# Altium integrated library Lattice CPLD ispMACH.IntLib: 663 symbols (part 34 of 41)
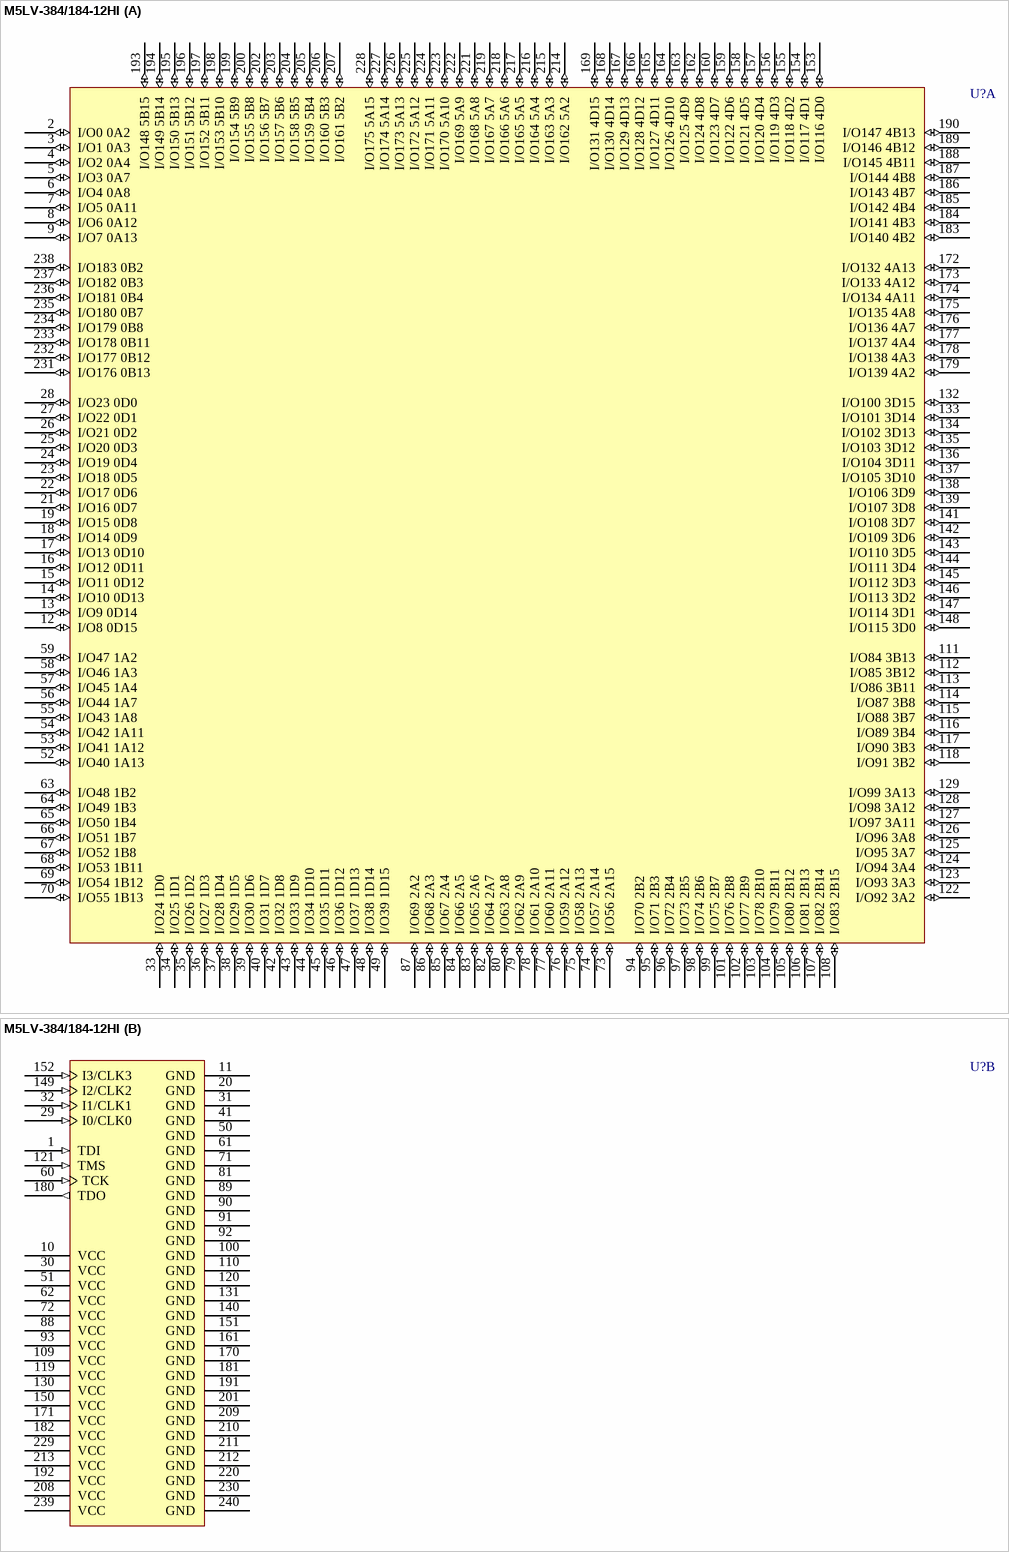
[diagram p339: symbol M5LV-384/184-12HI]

## M5LV-384/184-12HI
designator U?
High-Density and High-I/O Complex PLD
footprint PQFP240_N (Shrink QFP, 240-Leads, Body 32x32mm, Pitch 0.5mm, IPC Medium Density)
footprint PQFP240_L (Shrink QFP, 240-Leads, Body 32x32mm, Pitch 0.5mm, IPC High Density)
footprint PQFP240_M (Shrink QFP, 240-Leads, Body 32x32mm, Pitch 0.5mm, IPC Low Density)
3D model M5LV-PQFP240 (240-Pin Shrink Quad Flat Pack 0.5 mm Pitch)
part A pins: 2 I/O0 0A2 (io), 3 I/O1 0A3 (io), 4 I/O2 0A4 (io), 5 I/O3 0A7 (io), 6 I/O4 0A8 (io), 7 I/O5 0A11 (io), 8 I/O6 0A12 (io), 9 I/O7 0A13 (io), 12 I/O8 0D15 (io), 13 I/O9 0D14 (io), 14 I/O10 0D13 (io), 15 I/O11 0D12 (io), 16 I/O12 0D11 (io), 17 I/O13 0D10 (io), 18 I/O14 0D9 (io), 19 I/O15 0D8 (io), 21 I/O16 0D7 (io), 22 I/O17 0D6 (io), 23 I/O18 0D5 (io), 24 I/O19 0D4 (io), 25 I/O20 0D3 (io), 26 I/O21 0D2 (io), 27 I/O22 0D1 (io), 28 I/O23 0D0 (io), 33 I/O24 1D0 (io), 34 I/O25 1D1 (io), 35 I/O26 1D2 (io), 36 I/O27 1D3 (io), 37 I/O28 1D4 (io), 38 I/O29 1D5 (io), 39 I/O30 1D6 (io), 40 I/O31 1D7 (io), 42 I/O32 1D8 (io), 43 I/O33 1D9 (io), 44 I/O34 1D10 (io), 45 I/O35 1D11 (io), 46 I/O36 1D12 (io), 47 I/O37 1D13 (io), 48 I/O38 1D14 (io), 49 I/O39 1D15 (io), 52 I/O40 1A13 (io), 53 I/O41 1A12 (io), 54 I/O42 1A11 (io), 55 I/O43 1A8 (io), 56 I/O44 1A7 (io), 57 I/O45 1A4 (io), 58 I/O46 1A3 (io), 59 I/O47 1A2 (io), 63 I/O48 1B2 (io), 64 I/O49 1B3 (io), 65 I/O50 1B4 (io), 66 I/O51 1B7 (io), 67 I/O52 1B8 (io), 68 I/O53 1B11 (io), 69 I/O54 1B12 (io), 70 I/O55 1B13 (io), 73 I/O56 2A15 (io), 74 I/O57 2A14 (io), 75 I/O58 2A13 (io), 76 I/O59 2A12 (io), 77 I/O60 2A11 (io), 78 I/O61 2A10 (io), 79 I/O62 2A9 (io), 80 I/O63 2A8 (io), 82 I/O64 2A7 (io), 83 I/O65 2A6 (io), 84 I/O66 2A5 (io), 85 I/O67 2A4 (io), 86 I/O68 2A3 (io), 87 I/O69 2A2 (io), 94 I/O70 2B2 (io), 95 I/O71 2B3 (io), 96 I/O72 2B4 (io), 97 I/O73 2B5 (io), 98 I/O74 2B6 (io), 99 I/O75 2B7 (io), 101 I/O76 2B8 (io), 102 I/O77 2B9 (io), 103 I/O78 2B10 (io), 104 I/O79 2B11 (io), 105 I/O80 2B12 (io), 106 I/O81 2B13 (io), 107 I/O82 2B14 (io), 108 I/O83 2B15 (io), 111 I/O84 3B13 (io), 112 I/O85 3B12 (io), 113 I/O86 3B11 (io), 114 I/O87 3B8 (io), 115 I/O88 3B7 (io), 116 I/O89 3B4 (io), 117 I/O90 3B3 (io), 118 I/O91 3B2 (io), 122 I/O92 3A2 (io), 123 I/O93 3A3 (io), 124 I/O94 3A4 (io), 125 I/O95 3A7 (io), 126 I/O96 3A8 (io), 127 I/O97 3A11 (io), 128 I/O98 3A12 (io), 129 I/O99 3A13 (io), 132 I/O100 3D15 (io), 133 I/O101 3D14 (io), 134 I/O102 3D13 (io), 135 I/O103 3D12 (io), 136 I/O104 3D11 (io), 137 I/O105 3D10 (io), 138 I/O106 3D9 (io), 139 I/O107 3D8 (io), 141 I/O108 3D7 (io), 142 I/O109 3D6 (io), 143 I/O110 3D5 (io), 144 I/O111 3D4 (io), 145 I/O112 3D3 (io), 146 I/O113 3D2 (io), 147 I/O114 3D1 (io), 148 I/O115 3D0 (io), 153 I/O116 4D0 (io), 154 I/O117 4D1 (io), 155 I/O118 4D2 (io), 156 I/O119 4D3 (io), 157 I/O120 4D4 (io), 158 I/O121 4D5 (io), 159 I/O122 4D6 (io), 160 I/O123 4D7 (io), 162 I/O124 4D8 (io), 163 I/O125 4D9 (io), 164 I/O126 4D10 (io), 165 I/O127 4D11 (io), 166 I/O128 4D12 (io), 167 I/O129 4D13 (io), 168 I/O130 4D14 (io), 169 I/O131 4D15 (io), 172 I/O132 4A13 (io), 173 I/O133 4A12 (io), 174 I/O134 4A11 (io), 175 I/O135 4A8 (io), 176 I/O136 4A7 (io), 177 I/O137 4A4 (io), 178 I/O138 4A3 (io), 179 I/O139 4A2 (io), 183 I/O140 4B2 (io), 184 I/O141 4B3 (io), 185 I/O142 4B4 (io), 186 I/O143 4B7 (io), 187 I/O144 4B8 (io), 188 I/O145 4B11 (io), 189 I/O146 4B12 (io), 190 I/O147 4B13 (io), 193 I/O148 5B15 (io), 194 I/O149 5B14 (io), 195 I/O150 5B13 (io), 196 I/O151 5B12 (io), 197 I/O152 5B11 (io), 198 I/O153 5B10 (io), 199 I/O154 5B9 (io), 200 I/O155 5B8 (io), 202 I/O156 5B7 (io), 203 I/O157 5B6 (io), 204 I/O158 5B5 (io), 205 I/O159 5B4 (io), 206 I/O160 5B3 (io), 207 I/O161 5B2 (io), 214 I/O162 5A2 (io), 215 I/O163 5A3 (io), 216 I/O164 5A4 (io), 217 I/O165 5A5 (io), 218 I/O166 5A6 (io), 219 I/O167 5A7 (io), 221 I/O168 5A8 (io), 222 I/O169 5A9 (io), 223 I/O170 5A10 (io), 224 I/O171 5A11 (io), 225 I/O172 5A12 (io), 226 I/O173 5A13 (io), 227 I/O174 5A14 (io), 228 I/O175 5A15 (io), 231 I/O176 0B13 (io), 232 I/O177 0B12 (io), 233 I/O178 0B11 (io), 234 I/O179 0B8 (io), 235 I/O180 0B7 (io), 236 I/O181 0B4 (io), 237 I/O182 0B3 (io), 238 I/O183 0B2 (io)
part B pins: 1 TDI (in), 10 VCC (power), 11 GND (power), 20 GND (power), 29 I0/CLK0 (in), 30 VCC (power), 31 GND (power), 32 I1/CLK1 (in), 41 GND (power), 50 GND (power), 51 VCC (power), 60 TCK (in), 61 GND (power), 62 VCC (power), 71 GND (power), 72 VCC (power), 81 GND (power), 88 VCC (power), 89 GND (power), 90 GND (power), 91 GND (power), 92 GND (power), 93 VCC (power), 100 GND (power), 109 VCC (power), 110 GND (power), 119 VCC (power), 120 GND (power), 121 TMS (in), 130 VCC (power), 131 GND (power), 140 GND (power), 149 I2/CLK2 (in), 150 VCC (power), 151 GND (power), 152 I3/CLK3 (in), 161 GND (power), 170 GND (power), 171 VCC (power), 180 TDO (out), 181 GND (power), 182 VCC (power), 191 GND (power), 192 VCC (power), 201 GND (power), 208 VCC (power), 209 GND (power), 210 GND (power), 211 GND (power), 212 GND (power), 213 VCC (power), 220 GND (power), 229 VCC (power), 230 GND (power), 239 VCC (power), 240 GND (power)

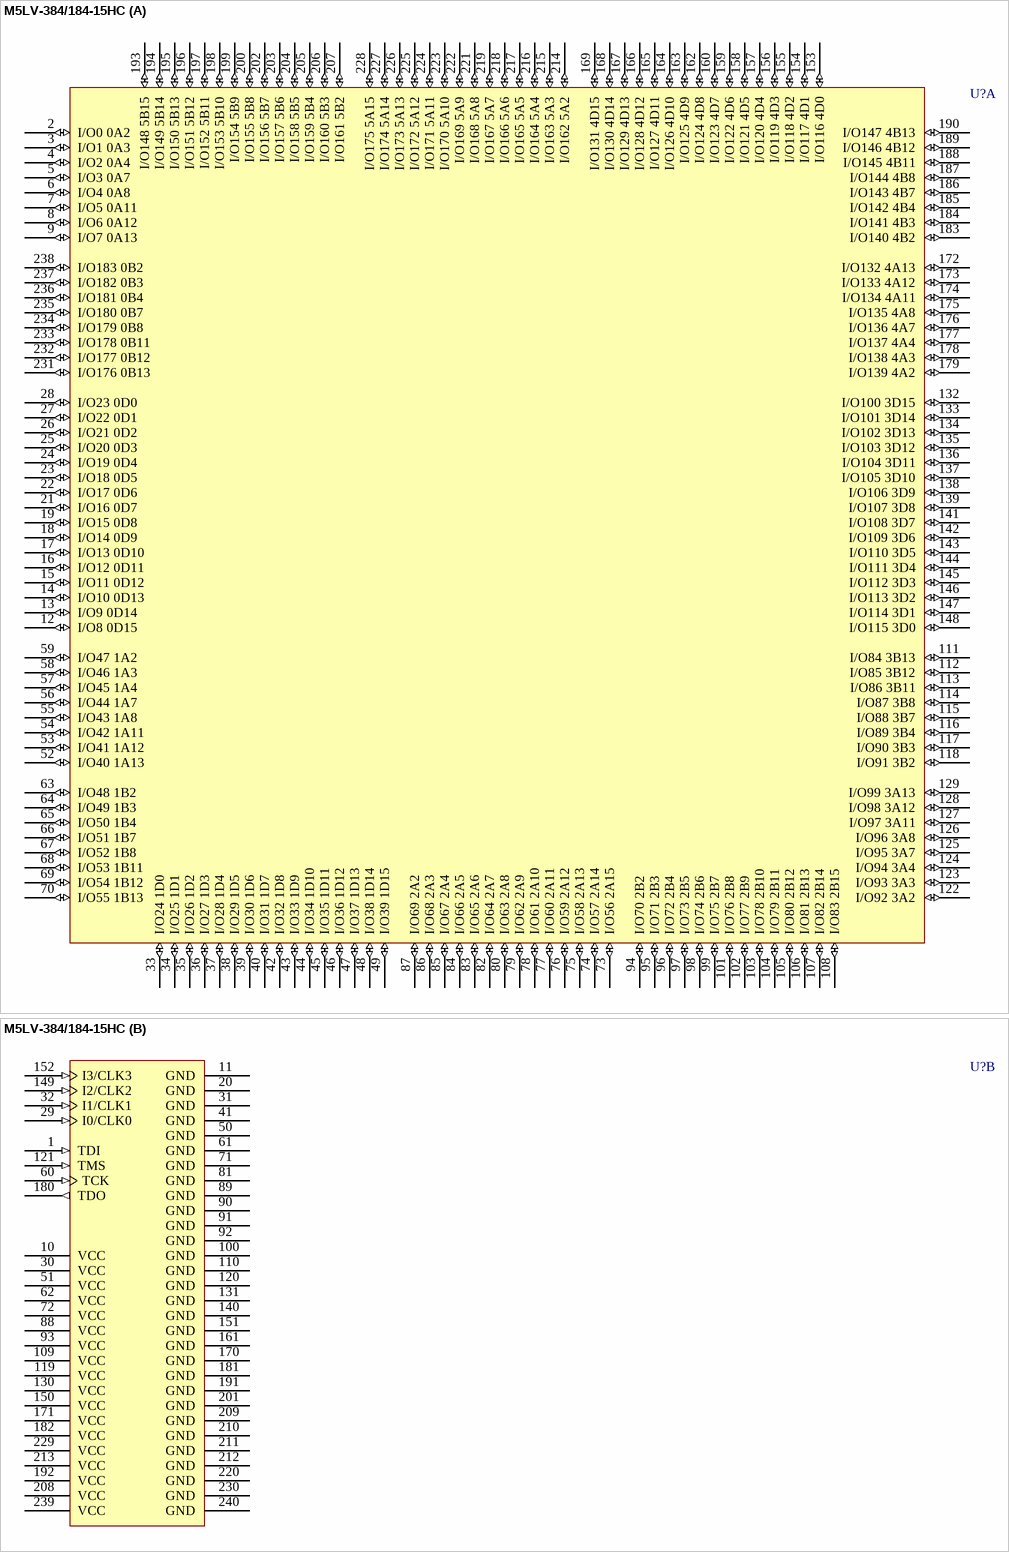
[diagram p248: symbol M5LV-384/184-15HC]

## M5LV-384/184-15HC
designator U?
High-Density and High-I/O Complex PLD
footprint PQFP240_N (Shrink QFP, 240-Leads, Body 32x32mm, Pitch 0.5mm, IPC Medium Density)
footprint PQFP240_L (Shrink QFP, 240-Leads, Body 32x32mm, Pitch 0.5mm, IPC High Density)
footprint PQFP240_M (Shrink QFP, 240-Leads, Body 32x32mm, Pitch 0.5mm, IPC Low Density)
3D model M5LV-PQFP240 (240-Pin Shrink Quad Flat Pack 0.5 mm Pitch)
part A pins: 2 I/O0 0A2 (io), 3 I/O1 0A3 (io), 4 I/O2 0A4 (io), 5 I/O3 0A7 (io), 6 I/O4 0A8 (io), 7 I/O5 0A11 (io), 8 I/O6 0A12 (io), 9 I/O7 0A13 (io), 12 I/O8 0D15 (io), 13 I/O9 0D14 (io), 14 I/O10 0D13 (io), 15 I/O11 0D12 (io), 16 I/O12 0D11 (io), 17 I/O13 0D10 (io), 18 I/O14 0D9 (io), 19 I/O15 0D8 (io), 21 I/O16 0D7 (io), 22 I/O17 0D6 (io), 23 I/O18 0D5 (io), 24 I/O19 0D4 (io), 25 I/O20 0D3 (io), 26 I/O21 0D2 (io), 27 I/O22 0D1 (io), 28 I/O23 0D0 (io), 33 I/O24 1D0 (io), 34 I/O25 1D1 (io), 35 I/O26 1D2 (io), 36 I/O27 1D3 (io), 37 I/O28 1D4 (io), 38 I/O29 1D5 (io), 39 I/O30 1D6 (io), 40 I/O31 1D7 (io), 42 I/O32 1D8 (io), 43 I/O33 1D9 (io), 44 I/O34 1D10 (io), 45 I/O35 1D11 (io), 46 I/O36 1D12 (io), 47 I/O37 1D13 (io), 48 I/O38 1D14 (io), 49 I/O39 1D15 (io), 52 I/O40 1A13 (io), 53 I/O41 1A12 (io), 54 I/O42 1A11 (io), 55 I/O43 1A8 (io), 56 I/O44 1A7 (io), 57 I/O45 1A4 (io), 58 I/O46 1A3 (io), 59 I/O47 1A2 (io), 63 I/O48 1B2 (io), 64 I/O49 1B3 (io), 65 I/O50 1B4 (io), 66 I/O51 1B7 (io), 67 I/O52 1B8 (io), 68 I/O53 1B11 (io), 69 I/O54 1B12 (io), 70 I/O55 1B13 (io), 73 I/O56 2A15 (io), 74 I/O57 2A14 (io), 75 I/O58 2A13 (io), 76 I/O59 2A12 (io), 77 I/O60 2A11 (io), 78 I/O61 2A10 (io), 79 I/O62 2A9 (io), 80 I/O63 2A8 (io), 82 I/O64 2A7 (io), 83 I/O65 2A6 (io), 84 I/O66 2A5 (io), 85 I/O67 2A4 (io), 86 I/O68 2A3 (io), 87 I/O69 2A2 (io), 94 I/O70 2B2 (io), 95 I/O71 2B3 (io), 96 I/O72 2B4 (io), 97 I/O73 2B5 (io), 98 I/O74 2B6 (io), 99 I/O75 2B7 (io), 101 I/O76 2B8 (io), 102 I/O77 2B9 (io), 103 I/O78 2B10 (io), 104 I/O79 2B11 (io), 105 I/O80 2B12 (io), 106 I/O81 2B13 (io), 107 I/O82 2B14 (io), 108 I/O83 2B15 (io), 111 I/O84 3B13 (io), 112 I/O85 3B12 (io), 113 I/O86 3B11 (io), 114 I/O87 3B8 (io), 115 I/O88 3B7 (io), 116 I/O89 3B4 (io), 117 I/O90 3B3 (io), 118 I/O91 3B2 (io), 122 I/O92 3A2 (io), 123 I/O93 3A3 (io), 124 I/O94 3A4 (io), 125 I/O95 3A7 (io), 126 I/O96 3A8 (io), 127 I/O97 3A11 (io), 128 I/O98 3A12 (io), 129 I/O99 3A13 (io), 132 I/O100 3D15 (io), 133 I/O101 3D14 (io), 134 I/O102 3D13 (io), 135 I/O103 3D12 (io), 136 I/O104 3D11 (io), 137 I/O105 3D10 (io), 138 I/O106 3D9 (io), 139 I/O107 3D8 (io), 141 I/O108 3D7 (io), 142 I/O109 3D6 (io), 143 I/O110 3D5 (io), 144 I/O111 3D4 (io), 145 I/O112 3D3 (io), 146 I/O113 3D2 (io), 147 I/O114 3D1 (io), 148 I/O115 3D0 (io), 153 I/O116 4D0 (io), 154 I/O117 4D1 (io), 155 I/O118 4D2 (io), 156 I/O119 4D3 (io), 157 I/O120 4D4 (io), 158 I/O121 4D5 (io), 159 I/O122 4D6 (io), 160 I/O123 4D7 (io), 162 I/O124 4D8 (io), 163 I/O125 4D9 (io), 164 I/O126 4D10 (io), 165 I/O127 4D11 (io), 166 I/O128 4D12 (io), 167 I/O129 4D13 (io), 168 I/O130 4D14 (io), 169 I/O131 4D15 (io), 172 I/O132 4A13 (io), 173 I/O133 4A12 (io), 174 I/O134 4A11 (io), 175 I/O135 4A8 (io), 176 I/O136 4A7 (io), 177 I/O137 4A4 (io), 178 I/O138 4A3 (io), 179 I/O139 4A2 (io), 183 I/O140 4B2 (io), 184 I/O141 4B3 (io), 185 I/O142 4B4 (io), 186 I/O143 4B7 (io), 187 I/O144 4B8 (io), 188 I/O145 4B11 (io), 189 I/O146 4B12 (io), 190 I/O147 4B13 (io), 193 I/O148 5B15 (io), 194 I/O149 5B14 (io), 195 I/O150 5B13 (io), 196 I/O151 5B12 (io), 197 I/O152 5B11 (io), 198 I/O153 5B10 (io), 199 I/O154 5B9 (io), 200 I/O155 5B8 (io), 202 I/O156 5B7 (io), 203 I/O157 5B6 (io), 204 I/O158 5B5 (io), 205 I/O159 5B4 (io), 206 I/O160 5B3 (io), 207 I/O161 5B2 (io), 214 I/O162 5A2 (io), 215 I/O163 5A3 (io), 216 I/O164 5A4 (io), 217 I/O165 5A5 (io), 218 I/O166 5A6 (io), 219 I/O167 5A7 (io), 221 I/O168 5A8 (io), 222 I/O169 5A9 (io), 223 I/O170 5A10 (io), 224 I/O171 5A11 (io), 225 I/O172 5A12 (io), 226 I/O173 5A13 (io), 227 I/O174 5A14 (io), 228 I/O175 5A15 (io), 231 I/O176 0B13 (io), 232 I/O177 0B12 (io), 233 I/O178 0B11 (io), 234 I/O179 0B8 (io), 235 I/O180 0B7 (io), 236 I/O181 0B4 (io), 237 I/O182 0B3 (io), 238 I/O183 0B2 (io)
part B pins: 1 TDI (in), 10 VCC (power), 11 GND (power), 20 GND (power), 29 I0/CLK0 (in), 30 VCC (power), 31 GND (power), 32 I1/CLK1 (in), 41 GND (power), 50 GND (power), 51 VCC (power), 60 TCK (in), 61 GND (power), 62 VCC (power), 71 GND (power), 72 VCC (power), 81 GND (power), 88 VCC (power), 89 GND (power), 90 GND (power), 91 GND (power), 92 GND (power), 93 VCC (power), 100 GND (power), 109 VCC (power), 110 GND (power), 119 VCC (power), 120 GND (power), 121 TMS (in), 130 VCC (power), 131 GND (power), 140 GND (power), 149 I2/CLK2 (in), 150 VCC (power), 151 GND (power), 152 I3/CLK3 (in), 161 GND (power), 170 GND (power), 171 VCC (power), 180 TDO (out), 181 GND (power), 182 VCC (power), 191 GND (power), 192 VCC (power), 201 GND (power), 208 VCC (power), 209 GND (power), 210 GND (power), 211 GND (power), 212 GND (power), 213 VCC (power), 220 GND (power), 229 VCC (power), 230 GND (power), 239 VCC (power), 240 GND (power)

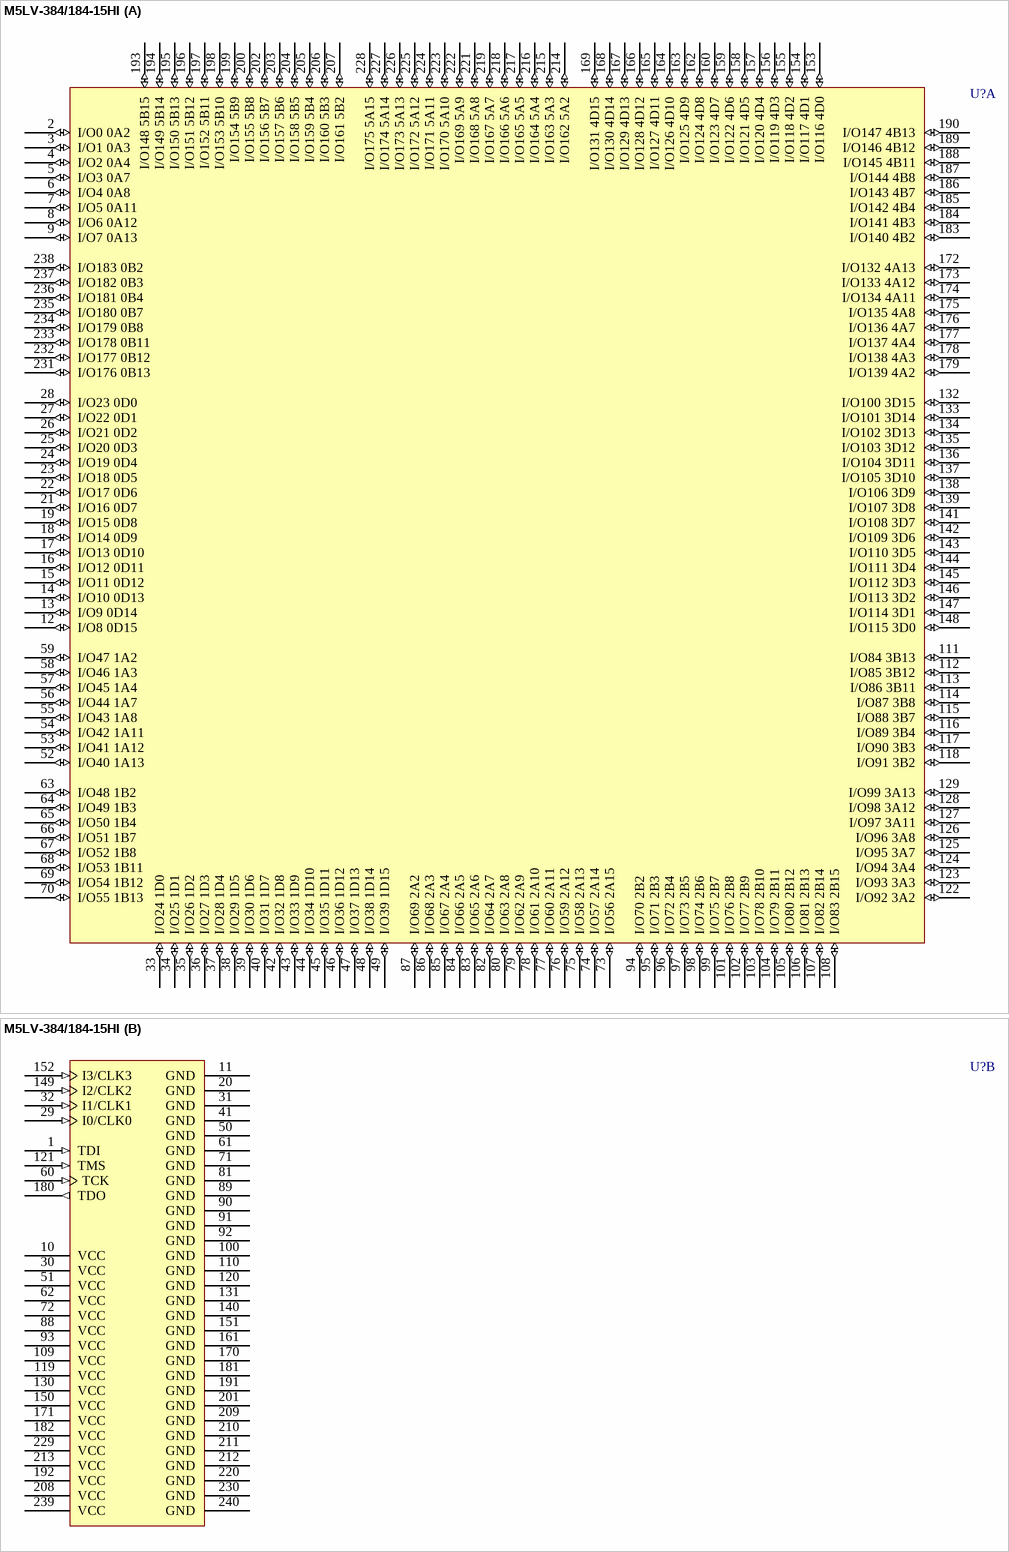
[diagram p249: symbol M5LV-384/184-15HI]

## M5LV-384/184-15HI
designator U?
High-Density and High-I/O Complex PLD
footprint PQFP240_N (Shrink QFP, 240-Leads, Body 32x32mm, Pitch 0.5mm, IPC Medium Density)
footprint PQFP240_L (Shrink QFP, 240-Leads, Body 32x32mm, Pitch 0.5mm, IPC High Density)
footprint PQFP240_M (Shrink QFP, 240-Leads, Body 32x32mm, Pitch 0.5mm, IPC Low Density)
3D model M5LV-PQFP240 (240-Pin Shrink Quad Flat Pack 0.5 mm Pitch)
part A pins: 2 I/O0 0A2 (io), 3 I/O1 0A3 (io), 4 I/O2 0A4 (io), 5 I/O3 0A7 (io), 6 I/O4 0A8 (io), 7 I/O5 0A11 (io), 8 I/O6 0A12 (io), 9 I/O7 0A13 (io), 12 I/O8 0D15 (io), 13 I/O9 0D14 (io), 14 I/O10 0D13 (io), 15 I/O11 0D12 (io), 16 I/O12 0D11 (io), 17 I/O13 0D10 (io), 18 I/O14 0D9 (io), 19 I/O15 0D8 (io), 21 I/O16 0D7 (io), 22 I/O17 0D6 (io), 23 I/O18 0D5 (io), 24 I/O19 0D4 (io), 25 I/O20 0D3 (io), 26 I/O21 0D2 (io), 27 I/O22 0D1 (io), 28 I/O23 0D0 (io), 33 I/O24 1D0 (io), 34 I/O25 1D1 (io), 35 I/O26 1D2 (io), 36 I/O27 1D3 (io), 37 I/O28 1D4 (io), 38 I/O29 1D5 (io), 39 I/O30 1D6 (io), 40 I/O31 1D7 (io), 42 I/O32 1D8 (io), 43 I/O33 1D9 (io), 44 I/O34 1D10 (io), 45 I/O35 1D11 (io), 46 I/O36 1D12 (io), 47 I/O37 1D13 (io), 48 I/O38 1D14 (io), 49 I/O39 1D15 (io), 52 I/O40 1A13 (io), 53 I/O41 1A12 (io), 54 I/O42 1A11 (io), 55 I/O43 1A8 (io), 56 I/O44 1A7 (io), 57 I/O45 1A4 (io), 58 I/O46 1A3 (io), 59 I/O47 1A2 (io), 63 I/O48 1B2 (io), 64 I/O49 1B3 (io), 65 I/O50 1B4 (io), 66 I/O51 1B7 (io), 67 I/O52 1B8 (io), 68 I/O53 1B11 (io), 69 I/O54 1B12 (io), 70 I/O55 1B13 (io), 73 I/O56 2A15 (io), 74 I/O57 2A14 (io), 75 I/O58 2A13 (io), 76 I/O59 2A12 (io), 77 I/O60 2A11 (io), 78 I/O61 2A10 (io), 79 I/O62 2A9 (io), 80 I/O63 2A8 (io), 82 I/O64 2A7 (io), 83 I/O65 2A6 (io), 84 I/O66 2A5 (io), 85 I/O67 2A4 (io), 86 I/O68 2A3 (io), 87 I/O69 2A2 (io), 94 I/O70 2B2 (io), 95 I/O71 2B3 (io), 96 I/O72 2B4 (io), 97 I/O73 2B5 (io), 98 I/O74 2B6 (io), 99 I/O75 2B7 (io), 101 I/O76 2B8 (io), 102 I/O77 2B9 (io), 103 I/O78 2B10 (io), 104 I/O79 2B11 (io), 105 I/O80 2B12 (io), 106 I/O81 2B13 (io), 107 I/O82 2B14 (io), 108 I/O83 2B15 (io), 111 I/O84 3B13 (io), 112 I/O85 3B12 (io), 113 I/O86 3B11 (io), 114 I/O87 3B8 (io), 115 I/O88 3B7 (io), 116 I/O89 3B4 (io), 117 I/O90 3B3 (io), 118 I/O91 3B2 (io), 122 I/O92 3A2 (io), 123 I/O93 3A3 (io), 124 I/O94 3A4 (io), 125 I/O95 3A7 (io), 126 I/O96 3A8 (io), 127 I/O97 3A11 (io), 128 I/O98 3A12 (io), 129 I/O99 3A13 (io), 132 I/O100 3D15 (io), 133 I/O101 3D14 (io), 134 I/O102 3D13 (io), 135 I/O103 3D12 (io), 136 I/O104 3D11 (io), 137 I/O105 3D10 (io), 138 I/O106 3D9 (io), 139 I/O107 3D8 (io), 141 I/O108 3D7 (io), 142 I/O109 3D6 (io), 143 I/O110 3D5 (io), 144 I/O111 3D4 (io), 145 I/O112 3D3 (io), 146 I/O113 3D2 (io), 147 I/O114 3D1 (io), 148 I/O115 3D0 (io), 153 I/O116 4D0 (io), 154 I/O117 4D1 (io), 155 I/O118 4D2 (io), 156 I/O119 4D3 (io), 157 I/O120 4D4 (io), 158 I/O121 4D5 (io), 159 I/O122 4D6 (io), 160 I/O123 4D7 (io), 162 I/O124 4D8 (io), 163 I/O125 4D9 (io), 164 I/O126 4D10 (io), 165 I/O127 4D11 (io), 166 I/O128 4D12 (io), 167 I/O129 4D13 (io), 168 I/O130 4D14 (io), 169 I/O131 4D15 (io), 172 I/O132 4A13 (io), 173 I/O133 4A12 (io), 174 I/O134 4A11 (io), 175 I/O135 4A8 (io), 176 I/O136 4A7 (io), 177 I/O137 4A4 (io), 178 I/O138 4A3 (io), 179 I/O139 4A2 (io), 183 I/O140 4B2 (io), 184 I/O141 4B3 (io), 185 I/O142 4B4 (io), 186 I/O143 4B7 (io), 187 I/O144 4B8 (io), 188 I/O145 4B11 (io), 189 I/O146 4B12 (io), 190 I/O147 4B13 (io), 193 I/O148 5B15 (io), 194 I/O149 5B14 (io), 195 I/O150 5B13 (io), 196 I/O151 5B12 (io), 197 I/O152 5B11 (io), 198 I/O153 5B10 (io), 199 I/O154 5B9 (io), 200 I/O155 5B8 (io), 202 I/O156 5B7 (io), 203 I/O157 5B6 (io), 204 I/O158 5B5 (io), 205 I/O159 5B4 (io), 206 I/O160 5B3 (io), 207 I/O161 5B2 (io), 214 I/O162 5A2 (io), 215 I/O163 5A3 (io), 216 I/O164 5A4 (io), 217 I/O165 5A5 (io), 218 I/O166 5A6 (io), 219 I/O167 5A7 (io), 221 I/O168 5A8 (io), 222 I/O169 5A9 (io), 223 I/O170 5A10 (io), 224 I/O171 5A11 (io), 225 I/O172 5A12 (io), 226 I/O173 5A13 (io), 227 I/O174 5A14 (io), 228 I/O175 5A15 (io), 231 I/O176 0B13 (io), 232 I/O177 0B12 (io), 233 I/O178 0B11 (io), 234 I/O179 0B8 (io), 235 I/O180 0B7 (io), 236 I/O181 0B4 (io), 237 I/O182 0B3 (io), 238 I/O183 0B2 (io)
part B pins: 1 TDI (in), 10 VCC (power), 11 GND (power), 20 GND (power), 29 I0/CLK0 (in), 30 VCC (power), 31 GND (power), 32 I1/CLK1 (in), 41 GND (power), 50 GND (power), 51 VCC (power), 60 TCK (in), 61 GND (power), 62 VCC (power), 71 GND (power), 72 VCC (power), 81 GND (power), 88 VCC (power), 89 GND (power), 90 GND (power), 91 GND (power), 92 GND (power), 93 VCC (power), 100 GND (power), 109 VCC (power), 110 GND (power), 119 VCC (power), 120 GND (power), 121 TMS (in), 130 VCC (power), 131 GND (power), 140 GND (power), 149 I2/CLK2 (in), 150 VCC (power), 151 GND (power), 152 I3/CLK3 (in), 161 GND (power), 170 GND (power), 171 VCC (power), 180 TDO (out), 181 GND (power), 182 VCC (power), 191 GND (power), 192 VCC (power), 201 GND (power), 208 VCC (power), 209 GND (power), 210 GND (power), 211 GND (power), 212 GND (power), 213 VCC (power), 220 GND (power), 229 VCC (power), 230 GND (power), 239 VCC (power), 240 GND (power)

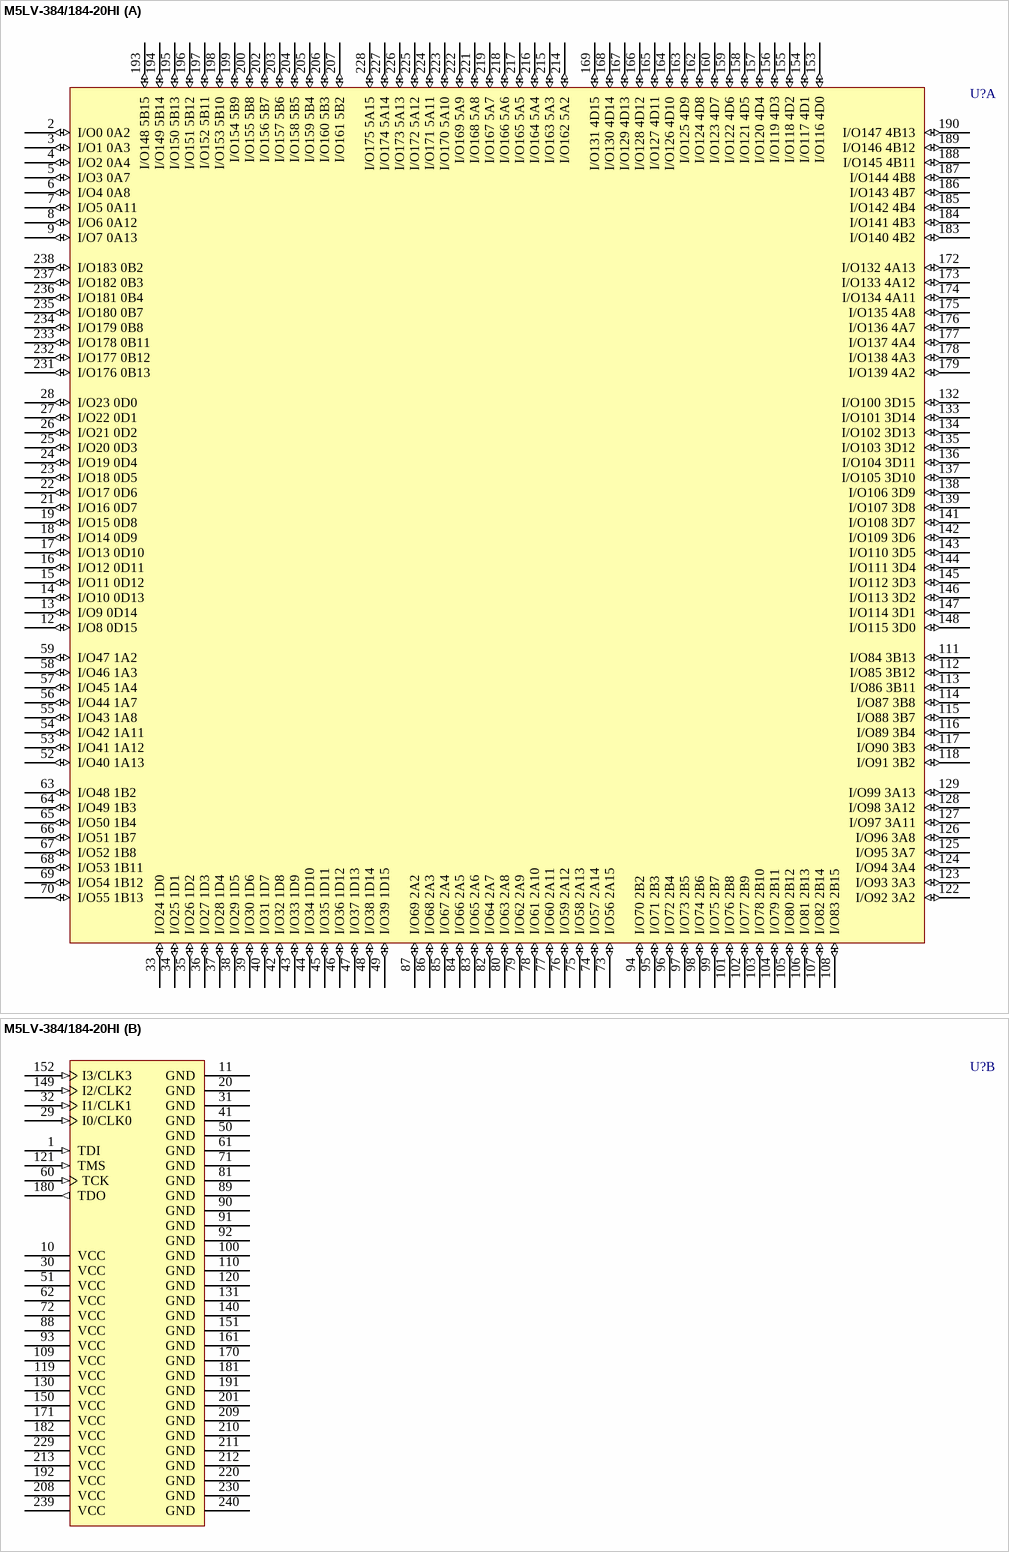
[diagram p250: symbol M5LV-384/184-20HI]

## M5LV-384/184-20HI
designator U?
High-Density and High-I/O Complex PLD
footprint PQFP240_N (Shrink QFP, 240-Leads, Body 32x32mm, Pitch 0.5mm, IPC Medium Density)
footprint PQFP240_L (Shrink QFP, 240-Leads, Body 32x32mm, Pitch 0.5mm, IPC High Density)
footprint PQFP240_M (Shrink QFP, 240-Leads, Body 32x32mm, Pitch 0.5mm, IPC Low Density)
3D model M5LV-PQFP240 (240-Pin Shrink Quad Flat Pack 0.5 mm Pitch)
part A pins: 2 I/O0 0A2 (io), 3 I/O1 0A3 (io), 4 I/O2 0A4 (io), 5 I/O3 0A7 (io), 6 I/O4 0A8 (io), 7 I/O5 0A11 (io), 8 I/O6 0A12 (io), 9 I/O7 0A13 (io), 12 I/O8 0D15 (io), 13 I/O9 0D14 (io), 14 I/O10 0D13 (io), 15 I/O11 0D12 (io), 16 I/O12 0D11 (io), 17 I/O13 0D10 (io), 18 I/O14 0D9 (io), 19 I/O15 0D8 (io), 21 I/O16 0D7 (io), 22 I/O17 0D6 (io), 23 I/O18 0D5 (io), 24 I/O19 0D4 (io), 25 I/O20 0D3 (io), 26 I/O21 0D2 (io), 27 I/O22 0D1 (io), 28 I/O23 0D0 (io), 33 I/O24 1D0 (io), 34 I/O25 1D1 (io), 35 I/O26 1D2 (io), 36 I/O27 1D3 (io), 37 I/O28 1D4 (io), 38 I/O29 1D5 (io), 39 I/O30 1D6 (io), 40 I/O31 1D7 (io), 42 I/O32 1D8 (io), 43 I/O33 1D9 (io), 44 I/O34 1D10 (io), 45 I/O35 1D11 (io), 46 I/O36 1D12 (io), 47 I/O37 1D13 (io), 48 I/O38 1D14 (io), 49 I/O39 1D15 (io), 52 I/O40 1A13 (io), 53 I/O41 1A12 (io), 54 I/O42 1A11 (io), 55 I/O43 1A8 (io), 56 I/O44 1A7 (io), 57 I/O45 1A4 (io), 58 I/O46 1A3 (io), 59 I/O47 1A2 (io), 63 I/O48 1B2 (io), 64 I/O49 1B3 (io), 65 I/O50 1B4 (io), 66 I/O51 1B7 (io), 67 I/O52 1B8 (io), 68 I/O53 1B11 (io), 69 I/O54 1B12 (io), 70 I/O55 1B13 (io), 73 I/O56 2A15 (io), 74 I/O57 2A14 (io), 75 I/O58 2A13 (io), 76 I/O59 2A12 (io), 77 I/O60 2A11 (io), 78 I/O61 2A10 (io), 79 I/O62 2A9 (io), 80 I/O63 2A8 (io), 82 I/O64 2A7 (io), 83 I/O65 2A6 (io), 84 I/O66 2A5 (io), 85 I/O67 2A4 (io), 86 I/O68 2A3 (io), 87 I/O69 2A2 (io), 94 I/O70 2B2 (io), 95 I/O71 2B3 (io), 96 I/O72 2B4 (io), 97 I/O73 2B5 (io), 98 I/O74 2B6 (io), 99 I/O75 2B7 (io), 101 I/O76 2B8 (io), 102 I/O77 2B9 (io), 103 I/O78 2B10 (io), 104 I/O79 2B11 (io), 105 I/O80 2B12 (io), 106 I/O81 2B13 (io), 107 I/O82 2B14 (io), 108 I/O83 2B15 (io), 111 I/O84 3B13 (io), 112 I/O85 3B12 (io), 113 I/O86 3B11 (io), 114 I/O87 3B8 (io), 115 I/O88 3B7 (io), 116 I/O89 3B4 (io), 117 I/O90 3B3 (io), 118 I/O91 3B2 (io), 122 I/O92 3A2 (io), 123 I/O93 3A3 (io), 124 I/O94 3A4 (io), 125 I/O95 3A7 (io), 126 I/O96 3A8 (io), 127 I/O97 3A11 (io), 128 I/O98 3A12 (io), 129 I/O99 3A13 (io), 132 I/O100 3D15 (io), 133 I/O101 3D14 (io), 134 I/O102 3D13 (io), 135 I/O103 3D12 (io), 136 I/O104 3D11 (io), 137 I/O105 3D10 (io), 138 I/O106 3D9 (io), 139 I/O107 3D8 (io), 141 I/O108 3D7 (io), 142 I/O109 3D6 (io), 143 I/O110 3D5 (io), 144 I/O111 3D4 (io), 145 I/O112 3D3 (io), 146 I/O113 3D2 (io), 147 I/O114 3D1 (io), 148 I/O115 3D0 (io), 153 I/O116 4D0 (io), 154 I/O117 4D1 (io), 155 I/O118 4D2 (io), 156 I/O119 4D3 (io), 157 I/O120 4D4 (io), 158 I/O121 4D5 (io), 159 I/O122 4D6 (io), 160 I/O123 4D7 (io), 162 I/O124 4D8 (io), 163 I/O125 4D9 (io), 164 I/O126 4D10 (io), 165 I/O127 4D11 (io), 166 I/O128 4D12 (io), 167 I/O129 4D13 (io), 168 I/O130 4D14 (io), 169 I/O131 4D15 (io), 172 I/O132 4A13 (io), 173 I/O133 4A12 (io), 174 I/O134 4A11 (io), 175 I/O135 4A8 (io), 176 I/O136 4A7 (io), 177 I/O137 4A4 (io), 178 I/O138 4A3 (io), 179 I/O139 4A2 (io), 183 I/O140 4B2 (io), 184 I/O141 4B3 (io), 185 I/O142 4B4 (io), 186 I/O143 4B7 (io), 187 I/O144 4B8 (io), 188 I/O145 4B11 (io), 189 I/O146 4B12 (io), 190 I/O147 4B13 (io), 193 I/O148 5B15 (io), 194 I/O149 5B14 (io), 195 I/O150 5B13 (io), 196 I/O151 5B12 (io), 197 I/O152 5B11 (io), 198 I/O153 5B10 (io), 199 I/O154 5B9 (io), 200 I/O155 5B8 (io), 202 I/O156 5B7 (io), 203 I/O157 5B6 (io), 204 I/O158 5B5 (io), 205 I/O159 5B4 (io), 206 I/O160 5B3 (io), 207 I/O161 5B2 (io), 214 I/O162 5A2 (io), 215 I/O163 5A3 (io), 216 I/O164 5A4 (io), 217 I/O165 5A5 (io), 218 I/O166 5A6 (io), 219 I/O167 5A7 (io), 221 I/O168 5A8 (io), 222 I/O169 5A9 (io), 223 I/O170 5A10 (io), 224 I/O171 5A11 (io), 225 I/O172 5A12 (io), 226 I/O173 5A13 (io), 227 I/O174 5A14 (io), 228 I/O175 5A15 (io), 231 I/O176 0B13 (io), 232 I/O177 0B12 (io), 233 I/O178 0B11 (io), 234 I/O179 0B8 (io), 235 I/O180 0B7 (io), 236 I/O181 0B4 (io), 237 I/O182 0B3 (io), 238 I/O183 0B2 (io)
part B pins: 1 TDI (in), 10 VCC (power), 11 GND (power), 20 GND (power), 29 I0/CLK0 (in), 30 VCC (power), 31 GND (power), 32 I1/CLK1 (in), 41 GND (power), 50 GND (power), 51 VCC (power), 60 TCK (in), 61 GND (power), 62 VCC (power), 71 GND (power), 72 VCC (power), 81 GND (power), 88 VCC (power), 89 GND (power), 90 GND (power), 91 GND (power), 92 GND (power), 93 VCC (power), 100 GND (power), 109 VCC (power), 110 GND (power), 119 VCC (power), 120 GND (power), 121 TMS (in), 130 VCC (power), 131 GND (power), 140 GND (power), 149 I2/CLK2 (in), 150 VCC (power), 151 GND (power), 152 I3/CLK3 (in), 161 GND (power), 170 GND (power), 171 VCC (power), 180 TDO (out), 181 GND (power), 182 VCC (power), 191 GND (power), 192 VCC (power), 201 GND (power), 208 VCC (power), 209 GND (power), 210 GND (power), 211 GND (power), 212 GND (power), 213 VCC (power), 220 GND (power), 229 VCC (power), 230 GND (power), 239 VCC (power), 240 GND (power)

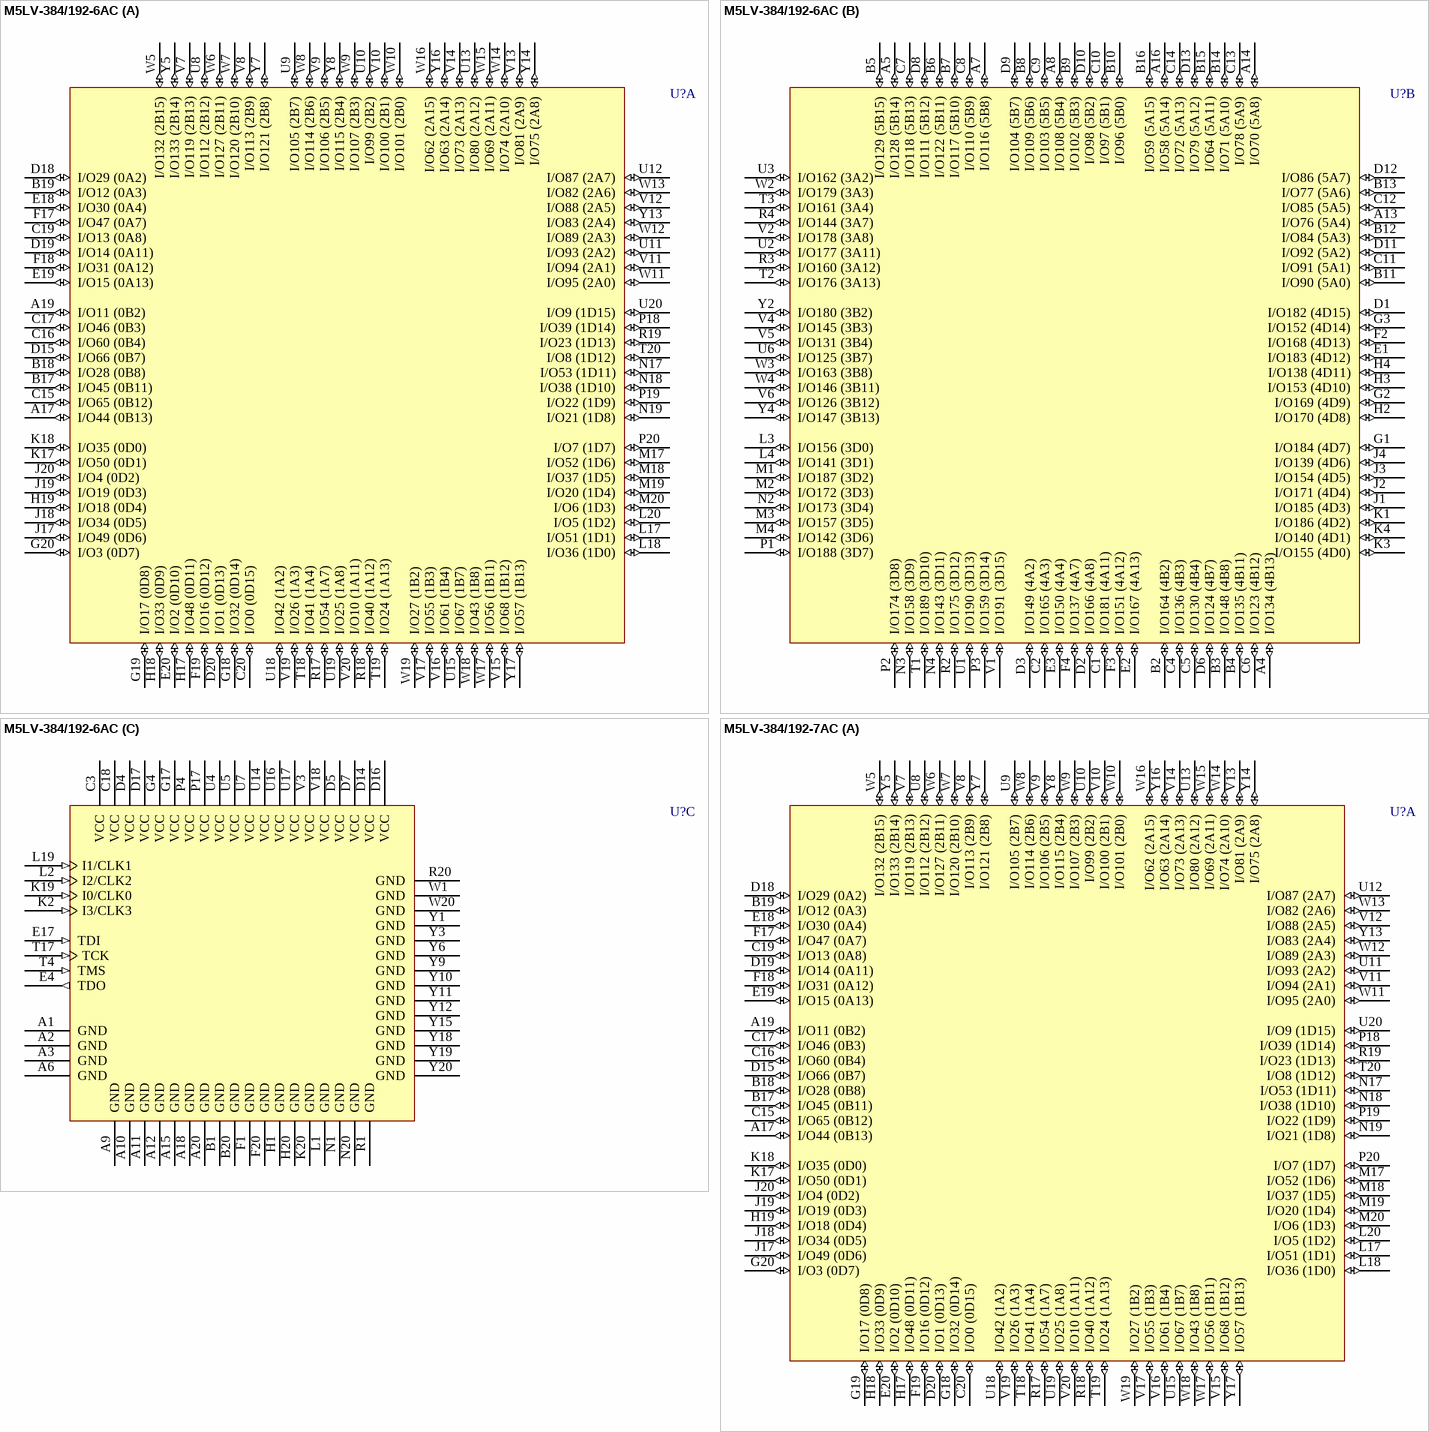
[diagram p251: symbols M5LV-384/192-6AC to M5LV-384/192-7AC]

## M5LV-384/192-6AC
designator U?
High-Density and High-I/O Complex PLD
footprint SBGA256 (BGA, 256-Leads, Body 27x27mm, Pitch 1.27mm)
3D model M5LV-SBGA256 (256-Ball Super Ball Grid Array (SBGA256))
part A pins: A17 I/O44 (0B13) (io), A19 I/O11 (0B2) (io), B17 I/O45 (0B11) (io), B18 I/O28 (0B8) (io), B19 I/O12 (0A3) (io), C15 I/O65 (0B12) (io), C16 I/O60 (0B4) (io), C17 I/O46 (0B3) (io), C19 I/O13 (0A8) (io), C20 I/O0 (0D15) (io), D15 I/O66 (0B7) (io), D18 I/O29 (0A2) (io), D19 I/O14 (0A11) (io), D20 I/O1 (0D13) (io), E18 I/O30 (0A4) (io), E19 I/O15 (0A13) (io), E20 I/O2 (0D10) (io), F17 I/O47 (0A7) (io), F18 I/O31 (0A12) (io), F19 I/O16 (0D12) (io), G18 I/O32 (0D14) (io), G19 I/O17 (0D8) (io), G20 I/O3 (0D7) (io), H17 I/O48 (0D11) (io), H18 I/O33 (0D9) (io), H19 I/O18 (0D4) (io), J17 I/O49 (0D6) (io), J18 I/O34 (0D5) (io), J19 I/O19 (0D3) (io), J20 I/O4 (0D2) (io), K17 I/O50 (0D1) (io), K18 I/O35 (0D0) (io), L17 I/O51 (1D1) (io), L18 I/O36 (1D0) (io), L20 I/O5 (1D2) (io), M17 I/O52 (1D6) (io), M18 I/O37 (1D5) (io), M19 I/O20 (1D4) (io), M20 I/O6 (1D3) (io), N17 I/O53 (1D11) (io), N18 I/O38 (1D10) (io), N19 I/O21 (1D8) (io), P18 I/O39 (1D14) (io), P19 I/O22 (1D9) (io), P20 I/O7 (1D7) (io), R17 I/O54 (1A7) (io), R18 I/O40 (1A12) (io), R19 I/O23 (1D13) (io), T18 I/O41 (1A4) (io), T19 I/O24 (1A13) (io), T20 I/O8 (1D12) (io), U8 I/O112 (2B12) (io), U9 I/O105 (2B7) (io), U10 I/O99 (2B2) (io), U11 I/O93 (2A2) (io), U12 I/O87 (2A7) (io), U13 I/O80 (2A12) (io), U15 I/O67 (1B7) (io), U18 I/O42 (1A2) (io), U19 I/O25 (1A8) (io), U20 I/O9 (1D15) (io), V7 I/O119 (2B13) (io), V8 I/O113 (2B9) (io), V9 I/O106 (2B5) (io), V10 I/O100 (2B1) (io), V11 I/O94 (2A1) (io), V12 I/O88 (2A5) (io), V13 I/O81 (2A9) (io), V14 I/O73 (2A13) (io), V15 I/O68 (1B12) (io), V16 I/O61 (1B4) (io), V17 I/O55 (1B3) (io), V19 I/O26 (1A3) (io), V20 I/O10 (1A11) (io), W5 I/O132 (2B15) (io), W6 I/O127 (2B11) (io), W7 I/O120 (2B10) (io), W8 I/O114 (2B6) (io), W9 I/O107 (2B3) (io), W10 I/O101 (2B0) (io), W11 I/O95 (2A0) (io), W12 I/O89 (2A3) (io), W13 I/O82 (2A6) (io), W14 I/O74 (2A10) (io), W15 I/O69 (2A11) (io), W16 I/O62 (2A15) (io), W17 I/O56 (1B11) (io), W18 I/O43 (1B8) (io), W19 I/O27 (1B2) (io), Y5 I/O133 (2B14) (io), Y7 I/O121 (2B8) (io), Y8 I/O115 (2B4) (io), Y13 I/O83 (2A4) (io), Y14 I/O75 (2A8) (io), Y16 I/O63 (2A14) (io), Y17 I/O57 (1B13) (io)
part B pins: A4 I/O134 (4B13) (io), A5 I/O128 (5B14) (io), A7 I/O116 (5B8) (io), A8 I/O108 (5B4) (io), A13 I/O76 (5A4) (io), A14 I/O70 (5A8) (io), A16 I/O58 (5A14) (io), B2 I/O164 (4B2) (io), B3 I/O148 (4B8) (io), B4 I/O135 (4B11) (io), B5 I/O129 (5B15) (io), B6 I/O122 (5B11) (io), B7 I/O117 (5B10) (io), B8 I/O109 (5B6) (io), B9 I/O102 (5B3) (io), B10 I/O96 (5B0) (io), B11 I/O90 (5A0) (io), B12 I/O84 (5A3) (io), B13 I/O77 (5A6) (io), B14 I/O71 (5A10) (io), B15 I/O64 (5A11) (io), B16 I/O59 (5A15) (io), C1 I/O181 (4A11) (io), C2 I/O165 (4A3) (io), C4 I/O136 (4B3) (io), C5 I/O130 (4B4) (io), C6 I/O123 (4B12) (io), C7 I/O118 (5B13) (io), C8 I/O110 (5B9) (io), C9 I/O103 (5B5) (io), C10 I/O97 (5B1) (io), C11 I/O91 (5A1) (io), C12 I/O85 (5A5) (io), C13 I/O78 (5A9) (io), C14 I/O72 (5A13) (io), D1 I/O182 (4D15) (io), D2 I/O166 (4A8) (io), D3 I/O149 (4A2) (io), D6 I/O124 (4B7) (io), D8 I/O111 (5B12) (io), D9 I/O104 (5B7) (io), D10 I/O98 (5B2) (io), D11 I/O92 (5A2) (io), D12 I/O86 (5A7) (io), D13 I/O79 (5A12) (io), E1 I/O183 (4D12) (io), E2 I/O167 (4A13) (io), E3 I/O150 (4A4) (io), F2 I/O168 (4D13) (io), F3 I/O151 (4A12) (io), F4 I/O137 (4A7) (io), G1 I/O184 (4D7) (io), G2 I/O169 (4D9) (io), G3 I/O152 (4D14) (io), H2 I/O170 (4D8) (io), H3 I/O153 (4D10) (io), H4 I/O138 (4D11) (io), J1 I/O185 (4D3) (io), J2 I/O171 (4D4) (io), J3 I/O154 (4D5) (io), J4 I/O139 (4D6) (io), K1 I/O186 (4D2) (io), K3 I/O155 (4D0) (io), K4 I/O140 (4D1) (io), L3 I/O156 (3D0) (io), L4 I/O141 (3D1) (io), M1 I/O187 (3D2) (io), M2 I/O172 (3D3) (io), M3 I/O157 (3D5) (io), M4 I/O142 (3D6) (io), N2 I/O173 (3D4) (io), N3 I/O158 (3D9) (io), N4 I/O143 (3D11) (io), P1 I/O188 (3D7) (io), P2 I/O174 (3D8) (io), P3 I/O159 (3D14) (io), R2 I/O175 (3D12) (io), R3 I/O160 (3A12) (io), R4 I/O144 (3A7) (io), T1 I/O189 (3D10) (io), T2 I/O176 (3A13) (io), T3 I/O161 (3A4) (io), U1 I/O190 (3D13) (io), U2 I/O177 (3A11) (io), U3 I/O162 (3A2) (io), U6 I/O125 (3B7) (io), V1 I/O191 (3D15) (io), V2 I/O178 (3A8) (io), V4 I/O145 (3B3) (io), V5 I/O131 (3B4) (io), V6 I/O126 (3B12) (io), W2 I/O179 (3A3) (io), W3 I/O163 (3B8) (io), W4 I/O146 (3B11) (io), Y2 I/O180 (3B2) (io), Y4 I/O147 (3B13) (io)
part C pins: A1 GND (power), A2 GND (power), A3 GND (power), A6 GND (power), A9 GND (power), A10 GND (power), A11 GND (power), A12 GND (power), A15 GND (power), A18 GND (power), A20 GND (power), B1 GND (power), B20 GND (power), C3 VCC (power), C18 VCC (power), D4 VCC (power), D5 VCC (power), D7 VCC (power), D14 VCC (power), D16 VCC (power), D17 VCC (power), E4 TDO (out), E17 TDI (in), F1 GND (power), F20 GND (power), G4 VCC (power), G17 VCC (power), H1 GND (power), H20 GND (power), K2 I3/CLK3 (in), K19 I0/CLK0 (in), K20 GND (power), L1 GND (power), L2 I2/CLK2 (in), L19 I1/CLK1 (in), N1 GND (power), N20 GND (power), P4 VCC (power), P17 VCC (power), R1 GND (power), R20 GND (power), T4 TMS (in), T17 TCK (in), U4 VCC (power), U5 VCC (power), U7 VCC (power), U14 VCC (power), U16 VCC (power), U17 VCC (power), V3 VCC (power), V18 VCC (power), W1 GND (power), W20 GND (power), Y1 GND (power), Y3 GND (power), Y6 GND (power), Y9 GND (power), Y10 GND (power), Y11 GND (power), Y12 GND (power), Y15 GND (power), Y18 GND (power), Y19 GND (power), Y20 GND (power)

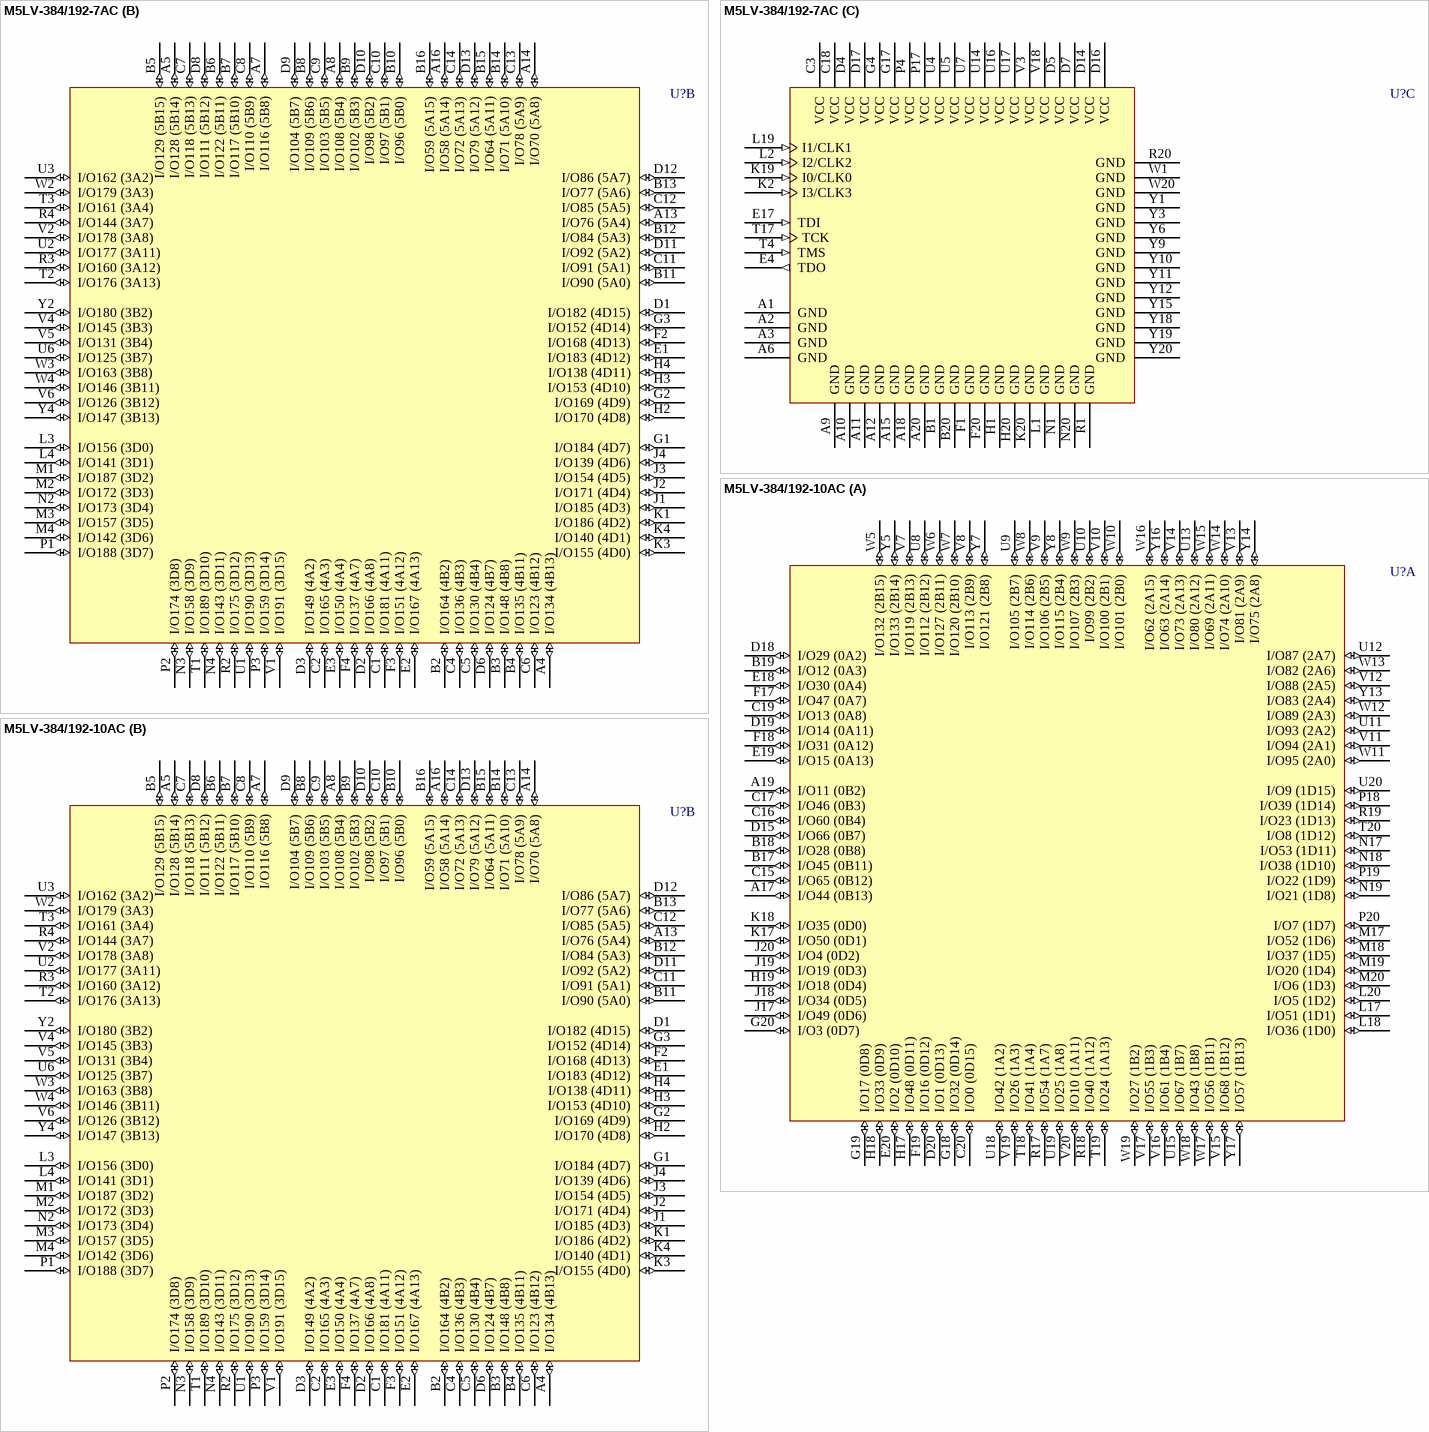
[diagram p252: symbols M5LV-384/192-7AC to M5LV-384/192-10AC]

## M5LV-384/192-7AC
designator U?
High-Density and High-I/O Complex PLD
footprint SBGA256 (BGA, 256-Leads, Body 27x27mm, Pitch 1.27mm)
3D model M5LV-SBGA256 (256-Ball Super Ball Grid Array (SBGA256))
part A pins: A17 I/O44 (0B13) (io), A19 I/O11 (0B2) (io), B17 I/O45 (0B11) (io), B18 I/O28 (0B8) (io), B19 I/O12 (0A3) (io), C15 I/O65 (0B12) (io), C16 I/O60 (0B4) (io), C17 I/O46 (0B3) (io), C19 I/O13 (0A8) (io), C20 I/O0 (0D15) (io), D15 I/O66 (0B7) (io), D18 I/O29 (0A2) (io), D19 I/O14 (0A11) (io), D20 I/O1 (0D13) (io), E18 I/O30 (0A4) (io), E19 I/O15 (0A13) (io), E20 I/O2 (0D10) (io), F17 I/O47 (0A7) (io), F18 I/O31 (0A12) (io), F19 I/O16 (0D12) (io), G18 I/O32 (0D14) (io), G19 I/O17 (0D8) (io), G20 I/O3 (0D7) (io), H17 I/O48 (0D11) (io), H18 I/O33 (0D9) (io), H19 I/O18 (0D4) (io), J17 I/O49 (0D6) (io), J18 I/O34 (0D5) (io), J19 I/O19 (0D3) (io), J20 I/O4 (0D2) (io), K17 I/O50 (0D1) (io), K18 I/O35 (0D0) (io), L17 I/O51 (1D1) (io), L18 I/O36 (1D0) (io), L20 I/O5 (1D2) (io), M17 I/O52 (1D6) (io), M18 I/O37 (1D5) (io), M19 I/O20 (1D4) (io), M20 I/O6 (1D3) (io), N17 I/O53 (1D11) (io), N18 I/O38 (1D10) (io), N19 I/O21 (1D8) (io), P18 I/O39 (1D14) (io), P19 I/O22 (1D9) (io), P20 I/O7 (1D7) (io), R17 I/O54 (1A7) (io), R18 I/O40 (1A12) (io), R19 I/O23 (1D13) (io), T18 I/O41 (1A4) (io), T19 I/O24 (1A13) (io), T20 I/O8 (1D12) (io), U8 I/O112 (2B12) (io), U9 I/O105 (2B7) (io), U10 I/O99 (2B2) (io), U11 I/O93 (2A2) (io), U12 I/O87 (2A7) (io), U13 I/O80 (2A12) (io), U15 I/O67 (1B7) (io), U18 I/O42 (1A2) (io), U19 I/O25 (1A8) (io), U20 I/O9 (1D15) (io), V7 I/O119 (2B13) (io), V8 I/O113 (2B9) (io), V9 I/O106 (2B5) (io), V10 I/O100 (2B1) (io), V11 I/O94 (2A1) (io), V12 I/O88 (2A5) (io), V13 I/O81 (2A9) (io), V14 I/O73 (2A13) (io), V15 I/O68 (1B12) (io), V16 I/O61 (1B4) (io), V17 I/O55 (1B3) (io), V19 I/O26 (1A3) (io), V20 I/O10 (1A11) (io), W5 I/O132 (2B15) (io), W6 I/O127 (2B11) (io), W7 I/O120 (2B10) (io), W8 I/O114 (2B6) (io), W9 I/O107 (2B3) (io), W10 I/O101 (2B0) (io), W11 I/O95 (2A0) (io), W12 I/O89 (2A3) (io), W13 I/O82 (2A6) (io), W14 I/O74 (2A10) (io), W15 I/O69 (2A11) (io), W16 I/O62 (2A15) (io), W17 I/O56 (1B11) (io), W18 I/O43 (1B8) (io), W19 I/O27 (1B2) (io), Y5 I/O133 (2B14) (io), Y7 I/O121 (2B8) (io), Y8 I/O115 (2B4) (io), Y13 I/O83 (2A4) (io), Y14 I/O75 (2A8) (io), Y16 I/O63 (2A14) (io), Y17 I/O57 (1B13) (io)
part B pins: A4 I/O134 (4B13) (io), A5 I/O128 (5B14) (io), A7 I/O116 (5B8) (io), A8 I/O108 (5B4) (io), A13 I/O76 (5A4) (io), A14 I/O70 (5A8) (io), A16 I/O58 (5A14) (io), B2 I/O164 (4B2) (io), B3 I/O148 (4B8) (io), B4 I/O135 (4B11) (io), B5 I/O129 (5B15) (io), B6 I/O122 (5B11) (io), B7 I/O117 (5B10) (io), B8 I/O109 (5B6) (io), B9 I/O102 (5B3) (io), B10 I/O96 (5B0) (io), B11 I/O90 (5A0) (io), B12 I/O84 (5A3) (io), B13 I/O77 (5A6) (io), B14 I/O71 (5A10) (io), B15 I/O64 (5A11) (io), B16 I/O59 (5A15) (io), C1 I/O181 (4A11) (io), C2 I/O165 (4A3) (io), C4 I/O136 (4B3) (io), C5 I/O130 (4B4) (io), C6 I/O123 (4B12) (io), C7 I/O118 (5B13) (io), C8 I/O110 (5B9) (io), C9 I/O103 (5B5) (io), C10 I/O97 (5B1) (io), C11 I/O91 (5A1) (io), C12 I/O85 (5A5) (io), C13 I/O78 (5A9) (io), C14 I/O72 (5A13) (io), D1 I/O182 (4D15) (io), D2 I/O166 (4A8) (io), D3 I/O149 (4A2) (io), D6 I/O124 (4B7) (io), D8 I/O111 (5B12) (io), D9 I/O104 (5B7) (io), D10 I/O98 (5B2) (io), D11 I/O92 (5A2) (io), D12 I/O86 (5A7) (io), D13 I/O79 (5A12) (io), E1 I/O183 (4D12) (io), E2 I/O167 (4A13) (io), E3 I/O150 (4A4) (io), F2 I/O168 (4D13) (io), F3 I/O151 (4A12) (io), F4 I/O137 (4A7) (io), G1 I/O184 (4D7) (io), G2 I/O169 (4D9) (io), G3 I/O152 (4D14) (io), H2 I/O170 (4D8) (io), H3 I/O153 (4D10) (io), H4 I/O138 (4D11) (io), J1 I/O185 (4D3) (io), J2 I/O171 (4D4) (io), J3 I/O154 (4D5) (io), J4 I/O139 (4D6) (io), K1 I/O186 (4D2) (io), K3 I/O155 (4D0) (io), K4 I/O140 (4D1) (io), L3 I/O156 (3D0) (io), L4 I/O141 (3D1) (io), M1 I/O187 (3D2) (io), M2 I/O172 (3D3) (io), M3 I/O157 (3D5) (io), M4 I/O142 (3D6) (io), N2 I/O173 (3D4) (io), N3 I/O158 (3D9) (io), N4 I/O143 (3D11) (io), P1 I/O188 (3D7) (io), P2 I/O174 (3D8) (io), P3 I/O159 (3D14) (io), R2 I/O175 (3D12) (io), R3 I/O160 (3A12) (io), R4 I/O144 (3A7) (io), T1 I/O189 (3D10) (io), T2 I/O176 (3A13) (io), T3 I/O161 (3A4) (io), U1 I/O190 (3D13) (io), U2 I/O177 (3A11) (io), U3 I/O162 (3A2) (io), U6 I/O125 (3B7) (io), V1 I/O191 (3D15) (io), V2 I/O178 (3A8) (io), V4 I/O145 (3B3) (io), V5 I/O131 (3B4) (io), V6 I/O126 (3B12) (io), W2 I/O179 (3A3) (io), W3 I/O163 (3B8) (io), W4 I/O146 (3B11) (io), Y2 I/O180 (3B2) (io), Y4 I/O147 (3B13) (io)
part C pins: A1 GND (power), A2 GND (power), A3 GND (power), A6 GND (power), A9 GND (power), A10 GND (power), A11 GND (power), A12 GND (power), A15 GND (power), A18 GND (power), A20 GND (power), B1 GND (power), B20 GND (power), C3 VCC (power), C18 VCC (power), D4 VCC (power), D5 VCC (power), D7 VCC (power), D14 VCC (power), D16 VCC (power), D17 VCC (power), E4 TDO (out), E17 TDI (in), F1 GND (power), F20 GND (power), G4 VCC (power), G17 VCC (power), H1 GND (power), H20 GND (power), K2 I3/CLK3 (in), K19 I0/CLK0 (in), K20 GND (power), L1 GND (power), L2 I2/CLK2 (in), L19 I1/CLK1 (in), N1 GND (power), N20 GND (power), P4 VCC (power), P17 VCC (power), R1 GND (power), R20 GND (power), T4 TMS (in), T17 TCK (in), U4 VCC (power), U5 VCC (power), U7 VCC (power), U14 VCC (power), U16 VCC (power), U17 VCC (power), V3 VCC (power), V18 VCC (power), W1 GND (power), W20 GND (power), Y1 GND (power), Y3 GND (power), Y6 GND (power), Y9 GND (power), Y10 GND (power), Y11 GND (power), Y12 GND (power), Y15 GND (power), Y18 GND (power), Y19 GND (power), Y20 GND (power)

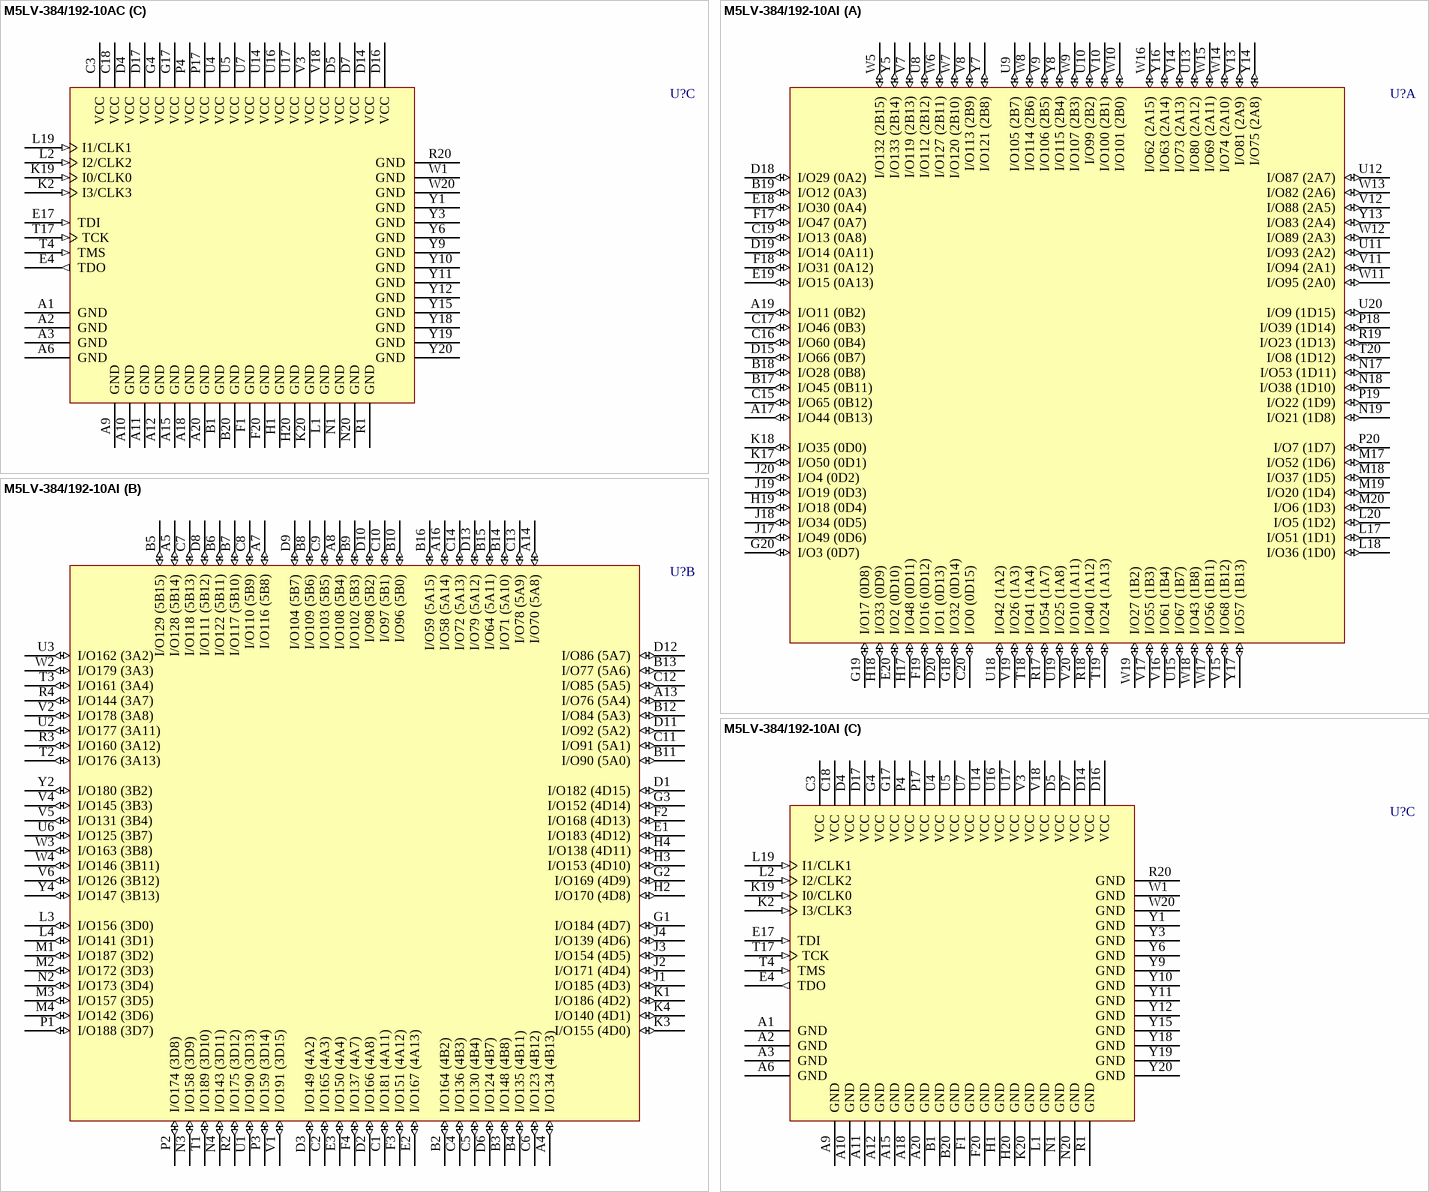
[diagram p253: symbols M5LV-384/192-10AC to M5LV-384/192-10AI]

## M5LV-384/192-10AC
designator U?
High-Density and High-I/O Complex PLD
footprint SBGA256 (BGA, 256-Leads, Body 27x27mm, Pitch 1.27mm)
3D model M5LV-SBGA256 (256-Ball Super Ball Grid Array (SBGA256))
part A pins: A17 I/O44 (0B13) (io), A19 I/O11 (0B2) (io), B17 I/O45 (0B11) (io), B18 I/O28 (0B8) (io), B19 I/O12 (0A3) (io), C15 I/O65 (0B12) (io), C16 I/O60 (0B4) (io), C17 I/O46 (0B3) (io), C19 I/O13 (0A8) (io), C20 I/O0 (0D15) (io), D15 I/O66 (0B7) (io), D18 I/O29 (0A2) (io), D19 I/O14 (0A11) (io), D20 I/O1 (0D13) (io), E18 I/O30 (0A4) (io), E19 I/O15 (0A13) (io), E20 I/O2 (0D10) (io), F17 I/O47 (0A7) (io), F18 I/O31 (0A12) (io), F19 I/O16 (0D12) (io), G18 I/O32 (0D14) (io), G19 I/O17 (0D8) (io), G20 I/O3 (0D7) (io), H17 I/O48 (0D11) (io), H18 I/O33 (0D9) (io), H19 I/O18 (0D4) (io), J17 I/O49 (0D6) (io), J18 I/O34 (0D5) (io), J19 I/O19 (0D3) (io), J20 I/O4 (0D2) (io), K17 I/O50 (0D1) (io), K18 I/O35 (0D0) (io), L17 I/O51 (1D1) (io), L18 I/O36 (1D0) (io), L20 I/O5 (1D2) (io), M17 I/O52 (1D6) (io), M18 I/O37 (1D5) (io), M19 I/O20 (1D4) (io), M20 I/O6 (1D3) (io), N17 I/O53 (1D11) (io), N18 I/O38 (1D10) (io), N19 I/O21 (1D8) (io), P18 I/O39 (1D14) (io), P19 I/O22 (1D9) (io), P20 I/O7 (1D7) (io), R17 I/O54 (1A7) (io), R18 I/O40 (1A12) (io), R19 I/O23 (1D13) (io), T18 I/O41 (1A4) (io), T19 I/O24 (1A13) (io), T20 I/O8 (1D12) (io), U8 I/O112 (2B12) (io), U9 I/O105 (2B7) (io), U10 I/O99 (2B2) (io), U11 I/O93 (2A2) (io), U12 I/O87 (2A7) (io), U13 I/O80 (2A12) (io), U15 I/O67 (1B7) (io), U18 I/O42 (1A2) (io), U19 I/O25 (1A8) (io), U20 I/O9 (1D15) (io), V7 I/O119 (2B13) (io), V8 I/O113 (2B9) (io), V9 I/O106 (2B5) (io), V10 I/O100 (2B1) (io), V11 I/O94 (2A1) (io), V12 I/O88 (2A5) (io), V13 I/O81 (2A9) (io), V14 I/O73 (2A13) (io), V15 I/O68 (1B12) (io), V16 I/O61 (1B4) (io), V17 I/O55 (1B3) (io), V19 I/O26 (1A3) (io), V20 I/O10 (1A11) (io), W5 I/O132 (2B15) (io), W6 I/O127 (2B11) (io), W7 I/O120 (2B10) (io), W8 I/O114 (2B6) (io), W9 I/O107 (2B3) (io), W10 I/O101 (2B0) (io), W11 I/O95 (2A0) (io), W12 I/O89 (2A3) (io), W13 I/O82 (2A6) (io), W14 I/O74 (2A10) (io), W15 I/O69 (2A11) (io), W16 I/O62 (2A15) (io), W17 I/O56 (1B11) (io), W18 I/O43 (1B8) (io), W19 I/O27 (1B2) (io), Y5 I/O133 (2B14) (io), Y7 I/O121 (2B8) (io), Y8 I/O115 (2B4) (io), Y13 I/O83 (2A4) (io), Y14 I/O75 (2A8) (io), Y16 I/O63 (2A14) (io), Y17 I/O57 (1B13) (io)
part B pins: A4 I/O134 (4B13) (io), A5 I/O128 (5B14) (io), A7 I/O116 (5B8) (io), A8 I/O108 (5B4) (io), A13 I/O76 (5A4) (io), A14 I/O70 (5A8) (io), A16 I/O58 (5A14) (io), B2 I/O164 (4B2) (io), B3 I/O148 (4B8) (io), B4 I/O135 (4B11) (io), B5 I/O129 (5B15) (io), B6 I/O122 (5B11) (io), B7 I/O117 (5B10) (io), B8 I/O109 (5B6) (io), B9 I/O102 (5B3) (io), B10 I/O96 (5B0) (io), B11 I/O90 (5A0) (io), B12 I/O84 (5A3) (io), B13 I/O77 (5A6) (io), B14 I/O71 (5A10) (io), B15 I/O64 (5A11) (io), B16 I/O59 (5A15) (io), C1 I/O181 (4A11) (io), C2 I/O165 (4A3) (io), C4 I/O136 (4B3) (io), C5 I/O130 (4B4) (io), C6 I/O123 (4B12) (io), C7 I/O118 (5B13) (io), C8 I/O110 (5B9) (io), C9 I/O103 (5B5) (io), C10 I/O97 (5B1) (io), C11 I/O91 (5A1) (io), C12 I/O85 (5A5) (io), C13 I/O78 (5A9) (io), C14 I/O72 (5A13) (io), D1 I/O182 (4D15) (io), D2 I/O166 (4A8) (io), D3 I/O149 (4A2) (io), D6 I/O124 (4B7) (io), D8 I/O111 (5B12) (io), D9 I/O104 (5B7) (io), D10 I/O98 (5B2) (io), D11 I/O92 (5A2) (io), D12 I/O86 (5A7) (io), D13 I/O79 (5A12) (io), E1 I/O183 (4D12) (io), E2 I/O167 (4A13) (io), E3 I/O150 (4A4) (io), F2 I/O168 (4D13) (io), F3 I/O151 (4A12) (io), F4 I/O137 (4A7) (io), G1 I/O184 (4D7) (io), G2 I/O169 (4D9) (io), G3 I/O152 (4D14) (io), H2 I/O170 (4D8) (io), H3 I/O153 (4D10) (io), H4 I/O138 (4D11) (io), J1 I/O185 (4D3) (io), J2 I/O171 (4D4) (io), J3 I/O154 (4D5) (io), J4 I/O139 (4D6) (io), K1 I/O186 (4D2) (io), K3 I/O155 (4D0) (io), K4 I/O140 (4D1) (io), L3 I/O156 (3D0) (io), L4 I/O141 (3D1) (io), M1 I/O187 (3D2) (io), M2 I/O172 (3D3) (io), M3 I/O157 (3D5) (io), M4 I/O142 (3D6) (io), N2 I/O173 (3D4) (io), N3 I/O158 (3D9) (io), N4 I/O143 (3D11) (io), P1 I/O188 (3D7) (io), P2 I/O174 (3D8) (io), P3 I/O159 (3D14) (io), R2 I/O175 (3D12) (io), R3 I/O160 (3A12) (io), R4 I/O144 (3A7) (io), T1 I/O189 (3D10) (io), T2 I/O176 (3A13) (io), T3 I/O161 (3A4) (io), U1 I/O190 (3D13) (io), U2 I/O177 (3A11) (io), U3 I/O162 (3A2) (io), U6 I/O125 (3B7) (io), V1 I/O191 (3D15) (io), V2 I/O178 (3A8) (io), V4 I/O145 (3B3) (io), V5 I/O131 (3B4) (io), V6 I/O126 (3B12) (io), W2 I/O179 (3A3) (io), W3 I/O163 (3B8) (io), W4 I/O146 (3B11) (io), Y2 I/O180 (3B2) (io), Y4 I/O147 (3B13) (io)
part C pins: A1 GND (power), A2 GND (power), A3 GND (power), A6 GND (power), A9 GND (power), A10 GND (power), A11 GND (power), A12 GND (power), A15 GND (power), A18 GND (power), A20 GND (power), B1 GND (power), B20 GND (power), C3 VCC (power), C18 VCC (power), D4 VCC (power), D5 VCC (power), D7 VCC (power), D14 VCC (power), D16 VCC (power), D17 VCC (power), E4 TDO (out), E17 TDI (in), F1 GND (power), F20 GND (power), G4 VCC (power), G17 VCC (power), H1 GND (power), H20 GND (power), K2 I3/CLK3 (in), K19 I0/CLK0 (in), K20 GND (power), L1 GND (power), L2 I2/CLK2 (in), L19 I1/CLK1 (in), N1 GND (power), N20 GND (power), P4 VCC (power), P17 VCC (power), R1 GND (power), R20 GND (power), T4 TMS (in), T17 TCK (in), U4 VCC (power), U5 VCC (power), U7 VCC (power), U14 VCC (power), U16 VCC (power), U17 VCC (power), V3 VCC (power), V18 VCC (power), W1 GND (power), W20 GND (power), Y1 GND (power), Y3 GND (power), Y6 GND (power), Y9 GND (power), Y10 GND (power), Y11 GND (power), Y12 GND (power), Y15 GND (power), Y18 GND (power), Y19 GND (power), Y20 GND (power)

## M5LV-384/192-10AI
designator U?
High-Density and High-I/O Complex PLD
footprint SBGA256 (BGA, 256-Leads, Body 27x27mm, Pitch 1.27mm)
3D model M5LV-SBGA256 (256-Ball Super Ball Grid Array (SBGA256))
part A pins: A17 I/O44 (0B13) (io), A19 I/O11 (0B2) (io), B17 I/O45 (0B11) (io), B18 I/O28 (0B8) (io), B19 I/O12 (0A3) (io), C15 I/O65 (0B12) (io), C16 I/O60 (0B4) (io), C17 I/O46 (0B3) (io), C19 I/O13 (0A8) (io), C20 I/O0 (0D15) (io), D15 I/O66 (0B7) (io), D18 I/O29 (0A2) (io), D19 I/O14 (0A11) (io), D20 I/O1 (0D13) (io), E18 I/O30 (0A4) (io), E19 I/O15 (0A13) (io), E20 I/O2 (0D10) (io), F17 I/O47 (0A7) (io), F18 I/O31 (0A12) (io), F19 I/O16 (0D12) (io), G18 I/O32 (0D14) (io), G19 I/O17 (0D8) (io), G20 I/O3 (0D7) (io), H17 I/O48 (0D11) (io), H18 I/O33 (0D9) (io), H19 I/O18 (0D4) (io), J17 I/O49 (0D6) (io), J18 I/O34 (0D5) (io), J19 I/O19 (0D3) (io), J20 I/O4 (0D2) (io), K17 I/O50 (0D1) (io), K18 I/O35 (0D0) (io), L17 I/O51 (1D1) (io), L18 I/O36 (1D0) (io), L20 I/O5 (1D2) (io), M17 I/O52 (1D6) (io), M18 I/O37 (1D5) (io), M19 I/O20 (1D4) (io), M20 I/O6 (1D3) (io), N17 I/O53 (1D11) (io), N18 I/O38 (1D10) (io), N19 I/O21 (1D8) (io), P18 I/O39 (1D14) (io), P19 I/O22 (1D9) (io), P20 I/O7 (1D7) (io), R17 I/O54 (1A7) (io), R18 I/O40 (1A12) (io), R19 I/O23 (1D13) (io), T18 I/O41 (1A4) (io), T19 I/O24 (1A13) (io), T20 I/O8 (1D12) (io), U8 I/O112 (2B12) (io), U9 I/O105 (2B7) (io), U10 I/O99 (2B2) (io), U11 I/O93 (2A2) (io), U12 I/O87 (2A7) (io), U13 I/O80 (2A12) (io), U15 I/O67 (1B7) (io), U18 I/O42 (1A2) (io), U19 I/O25 (1A8) (io), U20 I/O9 (1D15) (io), V7 I/O119 (2B13) (io), V8 I/O113 (2B9) (io), V9 I/O106 (2B5) (io), V10 I/O100 (2B1) (io), V11 I/O94 (2A1) (io), V12 I/O88 (2A5) (io), V13 I/O81 (2A9) (io), V14 I/O73 (2A13) (io), V15 I/O68 (1B12) (io), V16 I/O61 (1B4) (io), V17 I/O55 (1B3) (io), V19 I/O26 (1A3) (io), V20 I/O10 (1A11) (io), W5 I/O132 (2B15) (io), W6 I/O127 (2B11) (io), W7 I/O120 (2B10) (io), W8 I/O114 (2B6) (io), W9 I/O107 (2B3) (io), W10 I/O101 (2B0) (io), W11 I/O95 (2A0) (io), W12 I/O89 (2A3) (io), W13 I/O82 (2A6) (io), W14 I/O74 (2A10) (io), W15 I/O69 (2A11) (io), W16 I/O62 (2A15) (io), W17 I/O56 (1B11) (io), W18 I/O43 (1B8) (io), W19 I/O27 (1B2) (io), Y5 I/O133 (2B14) (io), Y7 I/O121 (2B8) (io), Y8 I/O115 (2B4) (io), Y13 I/O83 (2A4) (io), Y14 I/O75 (2A8) (io), Y16 I/O63 (2A14) (io), Y17 I/O57 (1B13) (io)
part B pins: A4 I/O134 (4B13) (io), A5 I/O128 (5B14) (io), A7 I/O116 (5B8) (io), A8 I/O108 (5B4) (io), A13 I/O76 (5A4) (io), A14 I/O70 (5A8) (io), A16 I/O58 (5A14) (io), B2 I/O164 (4B2) (io), B3 I/O148 (4B8) (io), B4 I/O135 (4B11) (io), B5 I/O129 (5B15) (io), B6 I/O122 (5B11) (io), B7 I/O117 (5B10) (io), B8 I/O109 (5B6) (io), B9 I/O102 (5B3) (io), B10 I/O96 (5B0) (io), B11 I/O90 (5A0) (io), B12 I/O84 (5A3) (io), B13 I/O77 (5A6) (io), B14 I/O71 (5A10) (io), B15 I/O64 (5A11) (io), B16 I/O59 (5A15) (io), C1 I/O181 (4A11) (io), C2 I/O165 (4A3) (io), C4 I/O136 (4B3) (io), C5 I/O130 (4B4) (io), C6 I/O123 (4B12) (io), C7 I/O118 (5B13) (io), C8 I/O110 (5B9) (io), C9 I/O103 (5B5) (io), C10 I/O97 (5B1) (io), C11 I/O91 (5A1) (io), C12 I/O85 (5A5) (io), C13 I/O78 (5A9) (io), C14 I/O72 (5A13) (io), D1 I/O182 (4D15) (io), D2 I/O166 (4A8) (io), D3 I/O149 (4A2) (io), D6 I/O124 (4B7) (io), D8 I/O111 (5B12) (io), D9 I/O104 (5B7) (io), D10 I/O98 (5B2) (io), D11 I/O92 (5A2) (io), D12 I/O86 (5A7) (io), D13 I/O79 (5A12) (io), E1 I/O183 (4D12) (io), E2 I/O167 (4A13) (io), E3 I/O150 (4A4) (io), F2 I/O168 (4D13) (io), F3 I/O151 (4A12) (io), F4 I/O137 (4A7) (io), G1 I/O184 (4D7) (io), G2 I/O169 (4D9) (io), G3 I/O152 (4D14) (io), H2 I/O170 (4D8) (io), H3 I/O153 (4D10) (io), H4 I/O138 (4D11) (io), J1 I/O185 (4D3) (io), J2 I/O171 (4D4) (io), J3 I/O154 (4D5) (io), J4 I/O139 (4D6) (io), K1 I/O186 (4D2) (io), K3 I/O155 (4D0) (io), K4 I/O140 (4D1) (io), L3 I/O156 (3D0) (io), L4 I/O141 (3D1) (io), M1 I/O187 (3D2) (io), M2 I/O172 (3D3) (io), M3 I/O157 (3D5) (io), M4 I/O142 (3D6) (io), N2 I/O173 (3D4) (io), N3 I/O158 (3D9) (io), N4 I/O143 (3D11) (io), P1 I/O188 (3D7) (io), P2 I/O174 (3D8) (io), P3 I/O159 (3D14) (io), R2 I/O175 (3D12) (io), R3 I/O160 (3A12) (io), R4 I/O144 (3A7) (io), T1 I/O189 (3D10) (io), T2 I/O176 (3A13) (io), T3 I/O161 (3A4) (io), U1 I/O190 (3D13) (io), U2 I/O177 (3A11) (io), U3 I/O162 (3A2) (io), U6 I/O125 (3B7) (io), V1 I/O191 (3D15) (io), V2 I/O178 (3A8) (io), V4 I/O145 (3B3) (io), V5 I/O131 (3B4) (io), V6 I/O126 (3B12) (io), W2 I/O179 (3A3) (io), W3 I/O163 (3B8) (io), W4 I/O146 (3B11) (io), Y2 I/O180 (3B2) (io), Y4 I/O147 (3B13) (io)
part C pins: A1 GND (power), A2 GND (power), A3 GND (power), A6 GND (power), A9 GND (power), A10 GND (power), A11 GND (power), A12 GND (power), A15 GND (power), A18 GND (power), A20 GND (power), B1 GND (power), B20 GND (power), C3 VCC (power), C18 VCC (power), D4 VCC (power), D5 VCC (power), D7 VCC (power), D14 VCC (power), D16 VCC (power), D17 VCC (power), E4 TDO (out), E17 TDI (in), F1 GND (power), F20 GND (power), G4 VCC (power), G17 VCC (power), H1 GND (power), H20 GND (power), K2 I3/CLK3 (in), K19 I0/CLK0 (in), K20 GND (power), L1 GND (power), L2 I2/CLK2 (in), L19 I1/CLK1 (in), N1 GND (power), N20 GND (power), P4 VCC (power), P17 VCC (power), R1 GND (power), R20 GND (power), T4 TMS (in), T17 TCK (in), U4 VCC (power), U5 VCC (power), U7 VCC (power), U14 VCC (power), U16 VCC (power), U17 VCC (power), V3 VCC (power), V18 VCC (power), W1 GND (power), W20 GND (power), Y1 GND (power), Y3 GND (power), Y6 GND (power), Y9 GND (power), Y10 GND (power), Y11 GND (power), Y12 GND (power), Y15 GND (power), Y18 GND (power), Y19 GND (power), Y20 GND (power)

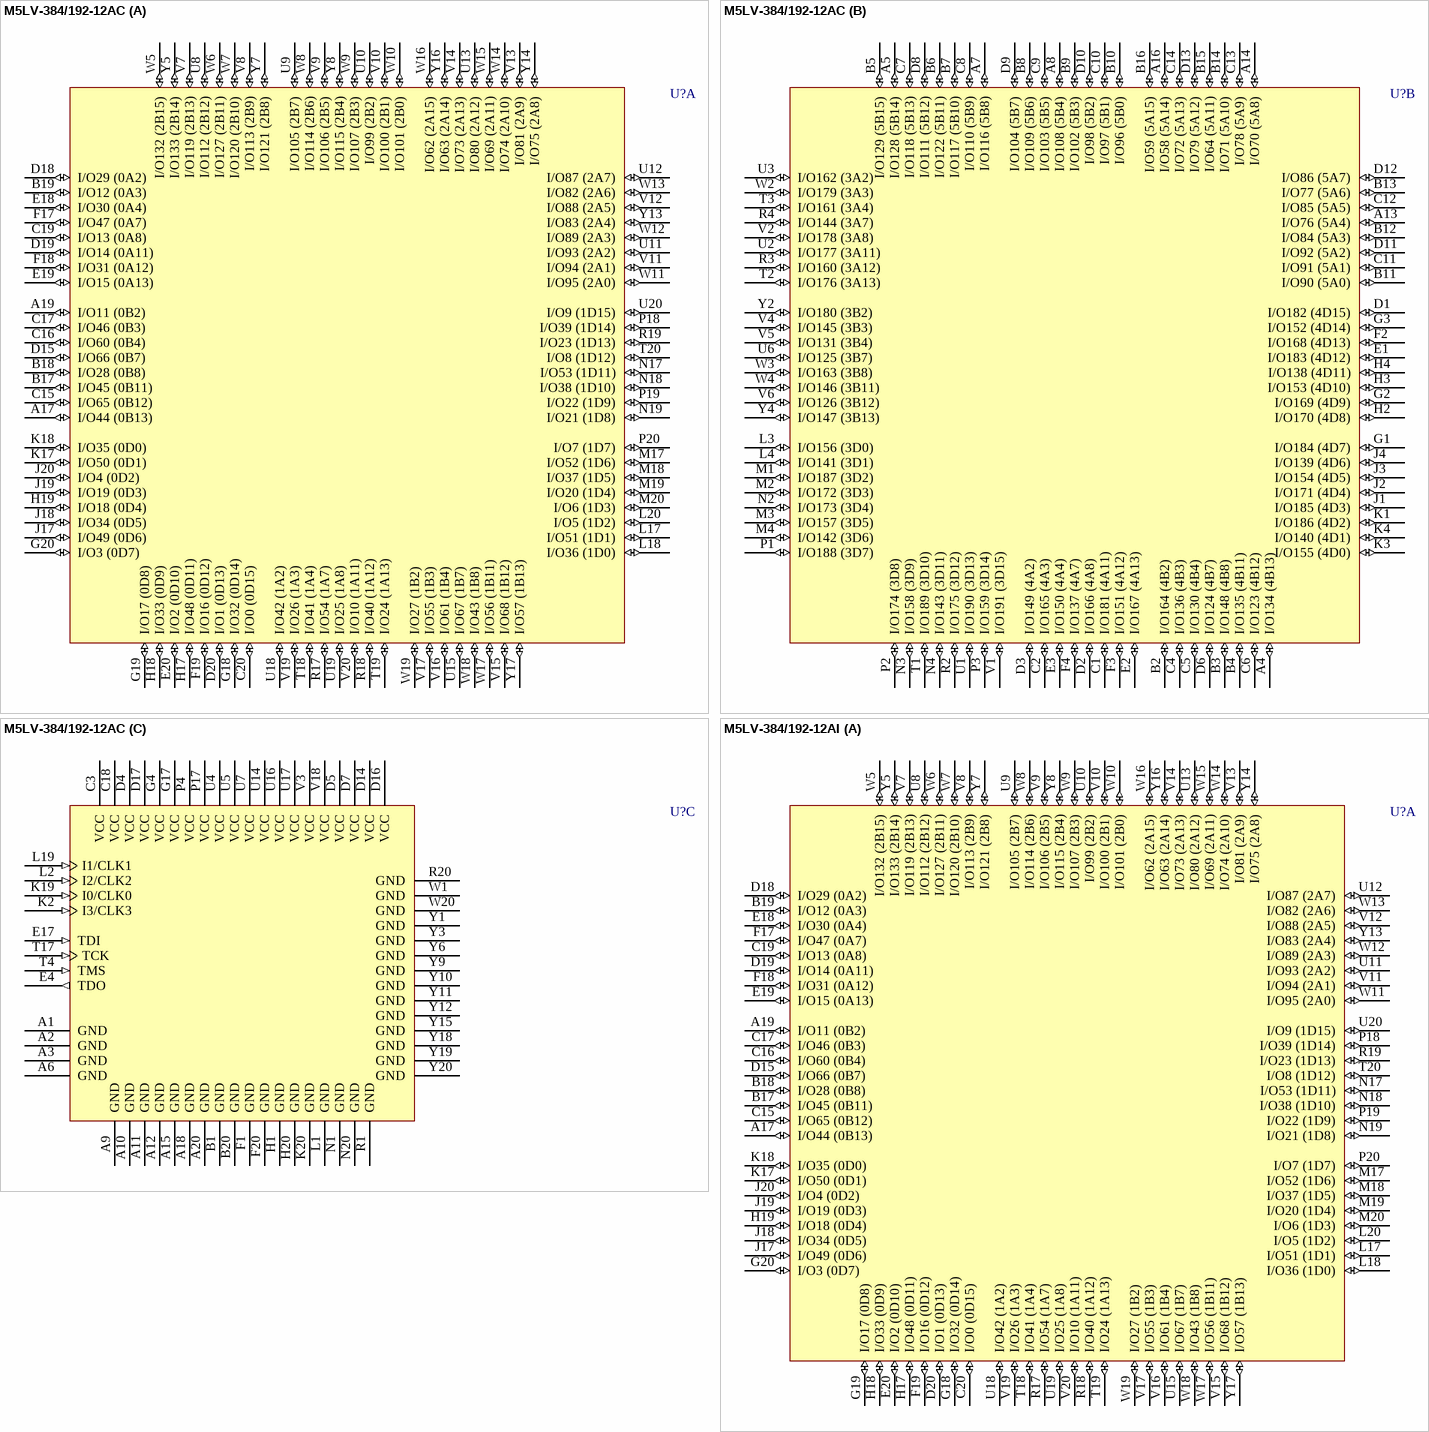
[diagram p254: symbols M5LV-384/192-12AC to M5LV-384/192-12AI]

## M5LV-384/192-12AC
designator U?
High-Density and High-I/O Complex PLD
footprint SBGA256 (BGA, 256-Leads, Body 27x27mm, Pitch 1.27mm)
3D model M5LV-SBGA256 (256-Ball Super Ball Grid Array (SBGA256))
part A pins: A17 I/O44 (0B13) (io), A19 I/O11 (0B2) (io), B17 I/O45 (0B11) (io), B18 I/O28 (0B8) (io), B19 I/O12 (0A3) (io), C15 I/O65 (0B12) (io), C16 I/O60 (0B4) (io), C17 I/O46 (0B3) (io), C19 I/O13 (0A8) (io), C20 I/O0 (0D15) (io), D15 I/O66 (0B7) (io), D18 I/O29 (0A2) (io), D19 I/O14 (0A11) (io), D20 I/O1 (0D13) (io), E18 I/O30 (0A4) (io), E19 I/O15 (0A13) (io), E20 I/O2 (0D10) (io), F17 I/O47 (0A7) (io), F18 I/O31 (0A12) (io), F19 I/O16 (0D12) (io), G18 I/O32 (0D14) (io), G19 I/O17 (0D8) (io), G20 I/O3 (0D7) (io), H17 I/O48 (0D11) (io), H18 I/O33 (0D9) (io), H19 I/O18 (0D4) (io), J17 I/O49 (0D6) (io), J18 I/O34 (0D5) (io), J19 I/O19 (0D3) (io), J20 I/O4 (0D2) (io), K17 I/O50 (0D1) (io), K18 I/O35 (0D0) (io), L17 I/O51 (1D1) (io), L18 I/O36 (1D0) (io), L20 I/O5 (1D2) (io), M17 I/O52 (1D6) (io), M18 I/O37 (1D5) (io), M19 I/O20 (1D4) (io), M20 I/O6 (1D3) (io), N17 I/O53 (1D11) (io), N18 I/O38 (1D10) (io), N19 I/O21 (1D8) (io), P18 I/O39 (1D14) (io), P19 I/O22 (1D9) (io), P20 I/O7 (1D7) (io), R17 I/O54 (1A7) (io), R18 I/O40 (1A12) (io), R19 I/O23 (1D13) (io), T18 I/O41 (1A4) (io), T19 I/O24 (1A13) (io), T20 I/O8 (1D12) (io), U8 I/O112 (2B12) (io), U9 I/O105 (2B7) (io), U10 I/O99 (2B2) (io), U11 I/O93 (2A2) (io), U12 I/O87 (2A7) (io), U13 I/O80 (2A12) (io), U15 I/O67 (1B7) (io), U18 I/O42 (1A2) (io), U19 I/O25 (1A8) (io), U20 I/O9 (1D15) (io), V7 I/O119 (2B13) (io), V8 I/O113 (2B9) (io), V9 I/O106 (2B5) (io), V10 I/O100 (2B1) (io), V11 I/O94 (2A1) (io), V12 I/O88 (2A5) (io), V13 I/O81 (2A9) (io), V14 I/O73 (2A13) (io), V15 I/O68 (1B12) (io), V16 I/O61 (1B4) (io), V17 I/O55 (1B3) (io), V19 I/O26 (1A3) (io), V20 I/O10 (1A11) (io), W5 I/O132 (2B15) (io), W6 I/O127 (2B11) (io), W7 I/O120 (2B10) (io), W8 I/O114 (2B6) (io), W9 I/O107 (2B3) (io), W10 I/O101 (2B0) (io), W11 I/O95 (2A0) (io), W12 I/O89 (2A3) (io), W13 I/O82 (2A6) (io), W14 I/O74 (2A10) (io), W15 I/O69 (2A11) (io), W16 I/O62 (2A15) (io), W17 I/O56 (1B11) (io), W18 I/O43 (1B8) (io), W19 I/O27 (1B2) (io), Y5 I/O133 (2B14) (io), Y7 I/O121 (2B8) (io), Y8 I/O115 (2B4) (io), Y13 I/O83 (2A4) (io), Y14 I/O75 (2A8) (io), Y16 I/O63 (2A14) (io), Y17 I/O57 (1B13) (io)
part B pins: A4 I/O134 (4B13) (io), A5 I/O128 (5B14) (io), A7 I/O116 (5B8) (io), A8 I/O108 (5B4) (io), A13 I/O76 (5A4) (io), A14 I/O70 (5A8) (io), A16 I/O58 (5A14) (io), B2 I/O164 (4B2) (io), B3 I/O148 (4B8) (io), B4 I/O135 (4B11) (io), B5 I/O129 (5B15) (io), B6 I/O122 (5B11) (io), B7 I/O117 (5B10) (io), B8 I/O109 (5B6) (io), B9 I/O102 (5B3) (io), B10 I/O96 (5B0) (io), B11 I/O90 (5A0) (io), B12 I/O84 (5A3) (io), B13 I/O77 (5A6) (io), B14 I/O71 (5A10) (io), B15 I/O64 (5A11) (io), B16 I/O59 (5A15) (io), C1 I/O181 (4A11) (io), C2 I/O165 (4A3) (io), C4 I/O136 (4B3) (io), C5 I/O130 (4B4) (io), C6 I/O123 (4B12) (io), C7 I/O118 (5B13) (io), C8 I/O110 (5B9) (io), C9 I/O103 (5B5) (io), C10 I/O97 (5B1) (io), C11 I/O91 (5A1) (io), C12 I/O85 (5A5) (io), C13 I/O78 (5A9) (io), C14 I/O72 (5A13) (io), D1 I/O182 (4D15) (io), D2 I/O166 (4A8) (io), D3 I/O149 (4A2) (io), D6 I/O124 (4B7) (io), D8 I/O111 (5B12) (io), D9 I/O104 (5B7) (io), D10 I/O98 (5B2) (io), D11 I/O92 (5A2) (io), D12 I/O86 (5A7) (io), D13 I/O79 (5A12) (io), E1 I/O183 (4D12) (io), E2 I/O167 (4A13) (io), E3 I/O150 (4A4) (io), F2 I/O168 (4D13) (io), F3 I/O151 (4A12) (io), F4 I/O137 (4A7) (io), G1 I/O184 (4D7) (io), G2 I/O169 (4D9) (io), G3 I/O152 (4D14) (io), H2 I/O170 (4D8) (io), H3 I/O153 (4D10) (io), H4 I/O138 (4D11) (io), J1 I/O185 (4D3) (io), J2 I/O171 (4D4) (io), J3 I/O154 (4D5) (io), J4 I/O139 (4D6) (io), K1 I/O186 (4D2) (io), K3 I/O155 (4D0) (io), K4 I/O140 (4D1) (io), L3 I/O156 (3D0) (io), L4 I/O141 (3D1) (io), M1 I/O187 (3D2) (io), M2 I/O172 (3D3) (io), M3 I/O157 (3D5) (io), M4 I/O142 (3D6) (io), N2 I/O173 (3D4) (io), N3 I/O158 (3D9) (io), N4 I/O143 (3D11) (io), P1 I/O188 (3D7) (io), P2 I/O174 (3D8) (io), P3 I/O159 (3D14) (io), R2 I/O175 (3D12) (io), R3 I/O160 (3A12) (io), R4 I/O144 (3A7) (io), T1 I/O189 (3D10) (io), T2 I/O176 (3A13) (io), T3 I/O161 (3A4) (io), U1 I/O190 (3D13) (io), U2 I/O177 (3A11) (io), U3 I/O162 (3A2) (io), U6 I/O125 (3B7) (io), V1 I/O191 (3D15) (io), V2 I/O178 (3A8) (io), V4 I/O145 (3B3) (io), V5 I/O131 (3B4) (io), V6 I/O126 (3B12) (io), W2 I/O179 (3A3) (io), W3 I/O163 (3B8) (io), W4 I/O146 (3B11) (io), Y2 I/O180 (3B2) (io), Y4 I/O147 (3B13) (io)
part C pins: A1 GND (power), A2 GND (power), A3 GND (power), A6 GND (power), A9 GND (power), A10 GND (power), A11 GND (power), A12 GND (power), A15 GND (power), A18 GND (power), A20 GND (power), B1 GND (power), B20 GND (power), C3 VCC (power), C18 VCC (power), D4 VCC (power), D5 VCC (power), D7 VCC (power), D14 VCC (power), D16 VCC (power), D17 VCC (power), E4 TDO (out), E17 TDI (in), F1 GND (power), F20 GND (power), G4 VCC (power), G17 VCC (power), H1 GND (power), H20 GND (power), K2 I3/CLK3 (in), K19 I0/CLK0 (in), K20 GND (power), L1 GND (power), L2 I2/CLK2 (in), L19 I1/CLK1 (in), N1 GND (power), N20 GND (power), P4 VCC (power), P17 VCC (power), R1 GND (power), R20 GND (power), T4 TMS (in), T17 TCK (in), U4 VCC (power), U5 VCC (power), U7 VCC (power), U14 VCC (power), U16 VCC (power), U17 VCC (power), V3 VCC (power), V18 VCC (power), W1 GND (power), W20 GND (power), Y1 GND (power), Y3 GND (power), Y6 GND (power), Y9 GND (power), Y10 GND (power), Y11 GND (power), Y12 GND (power), Y15 GND (power), Y18 GND (power), Y19 GND (power), Y20 GND (power)

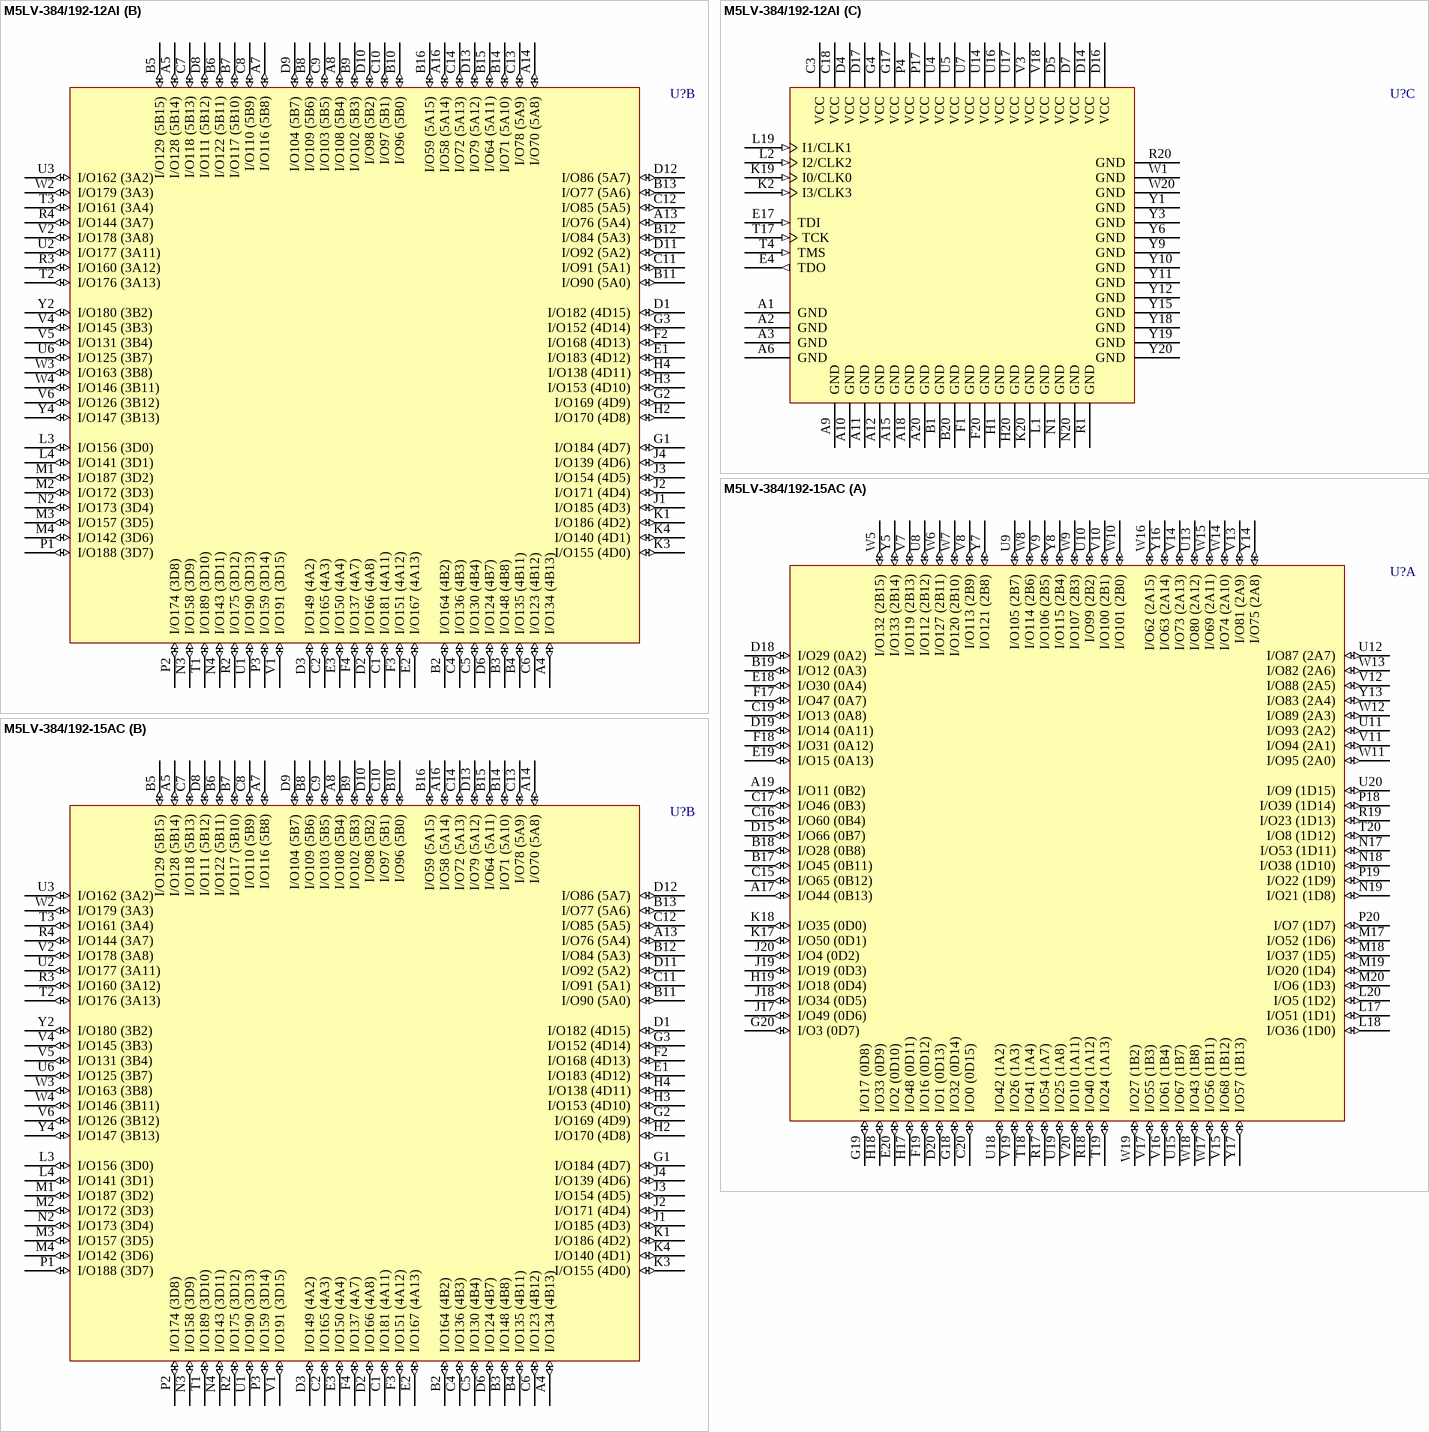
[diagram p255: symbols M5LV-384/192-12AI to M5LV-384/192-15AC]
